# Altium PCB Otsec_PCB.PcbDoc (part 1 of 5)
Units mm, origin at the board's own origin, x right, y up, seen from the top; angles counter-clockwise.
Board outline 170 x 120 mm, 3 copper layers (Top Layer, Internal Plane 1, Bottom Layer), stack 1.608 mm thick; 1624 components, 0 nets, 5478 pads, 0 vias.
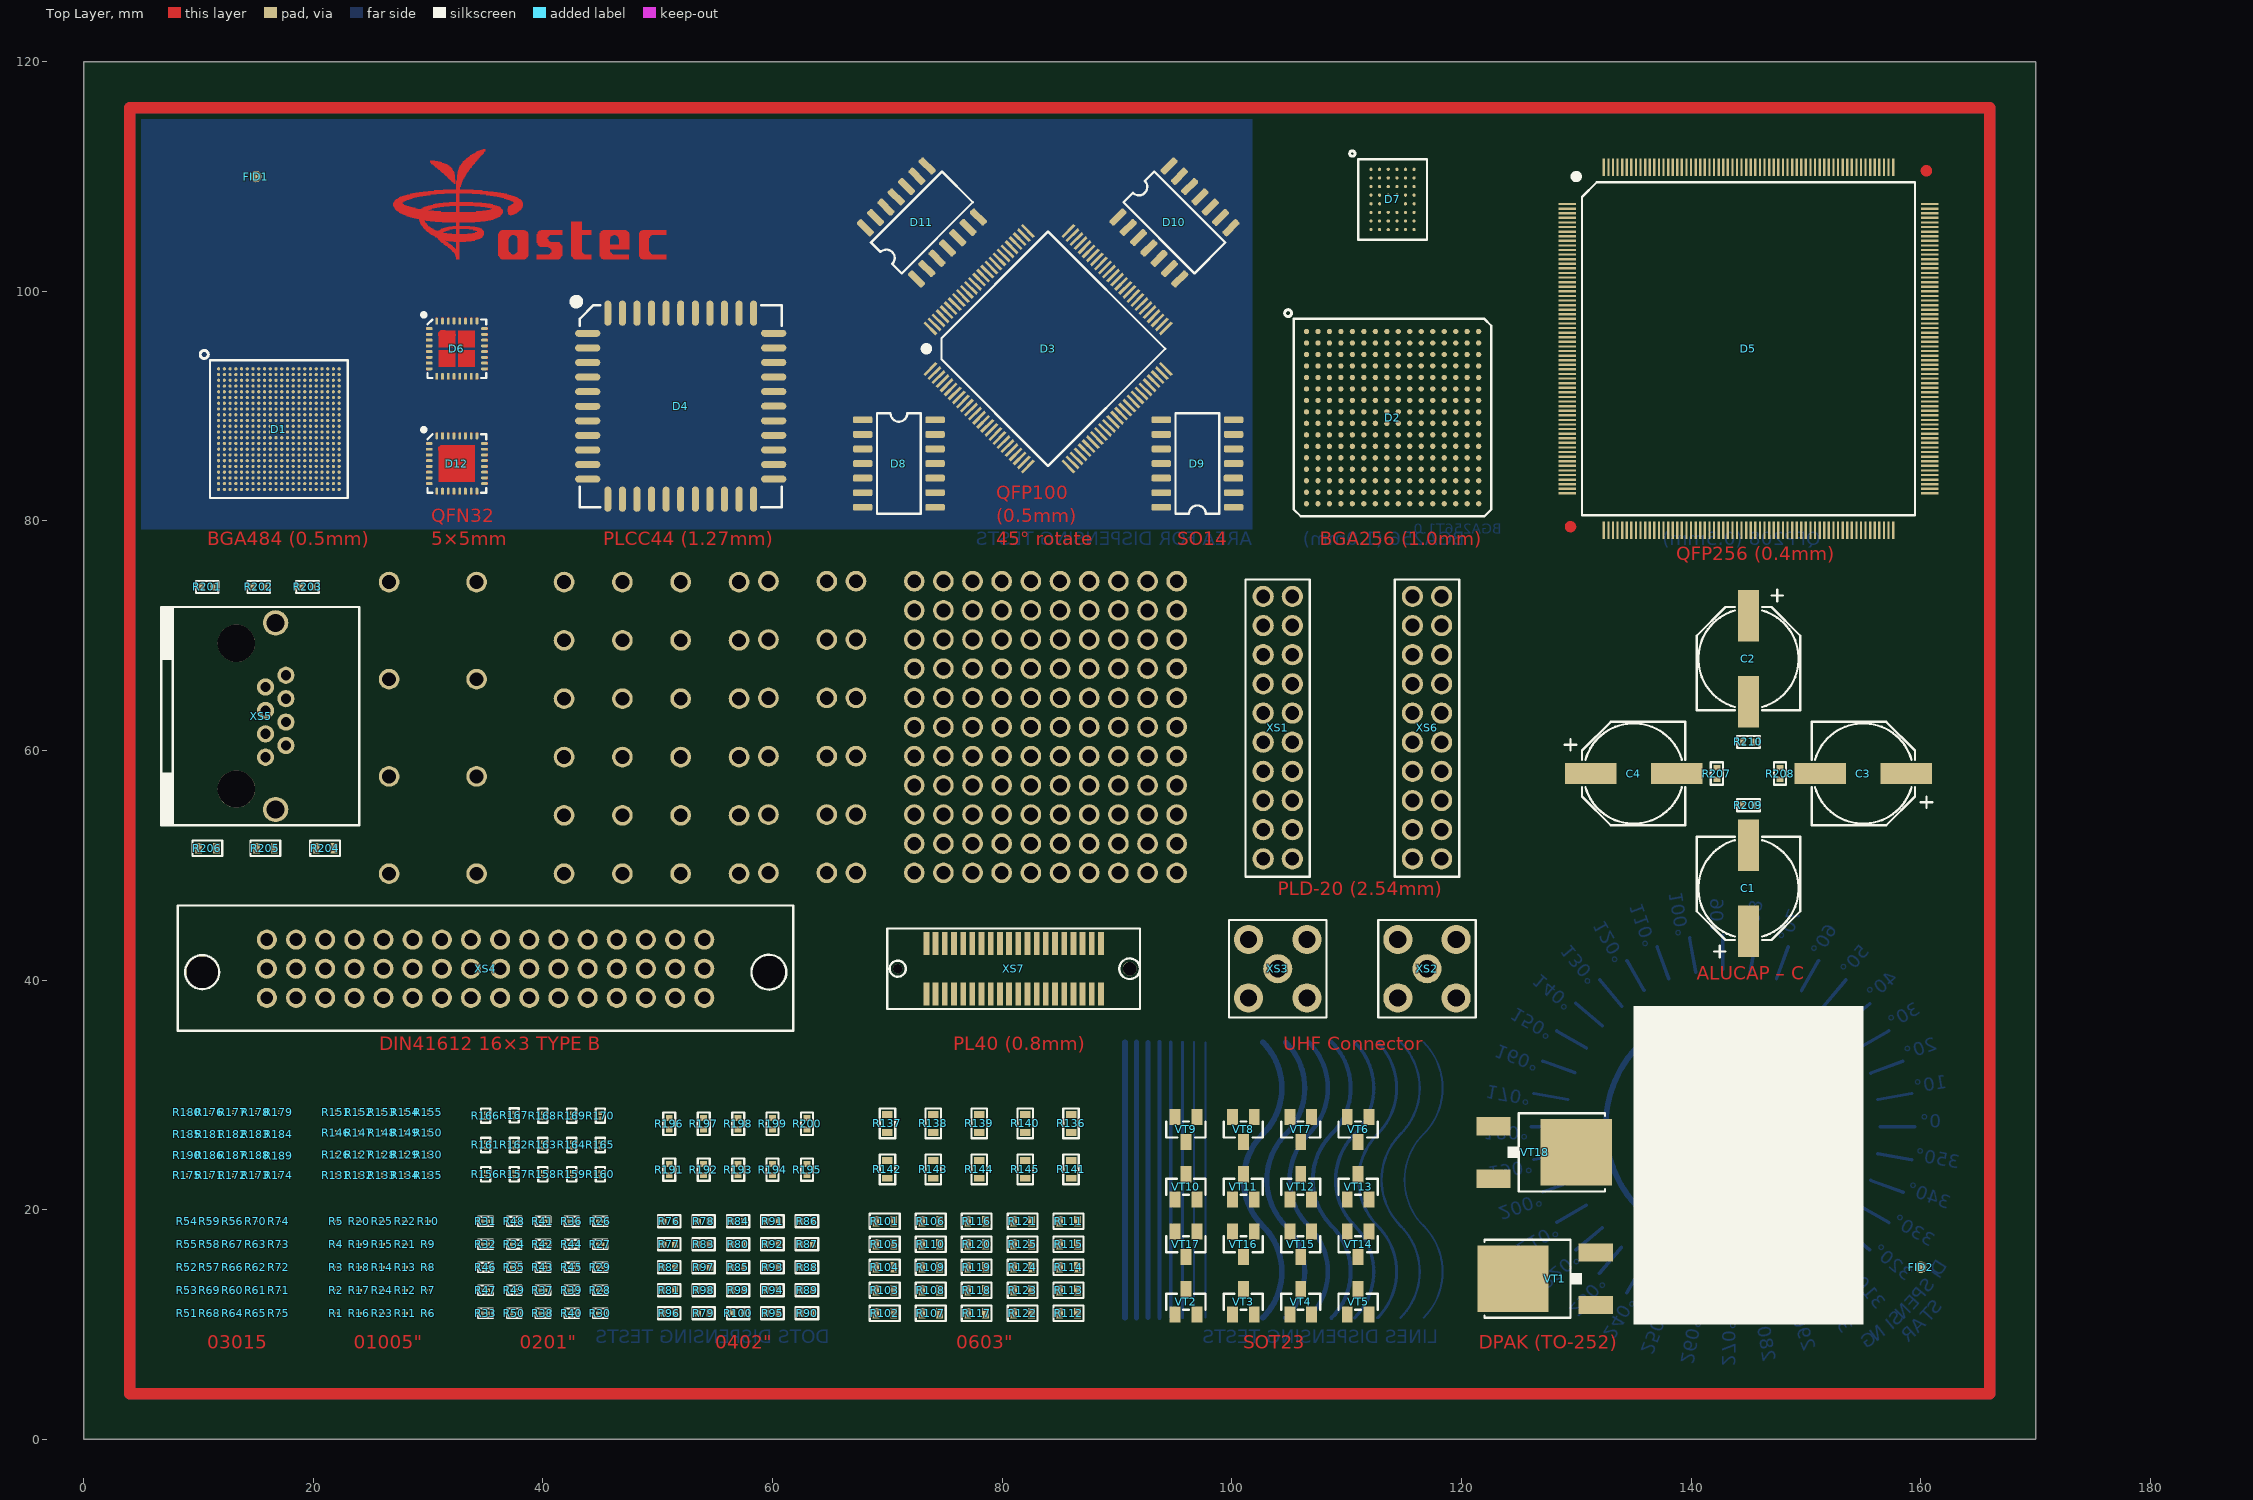
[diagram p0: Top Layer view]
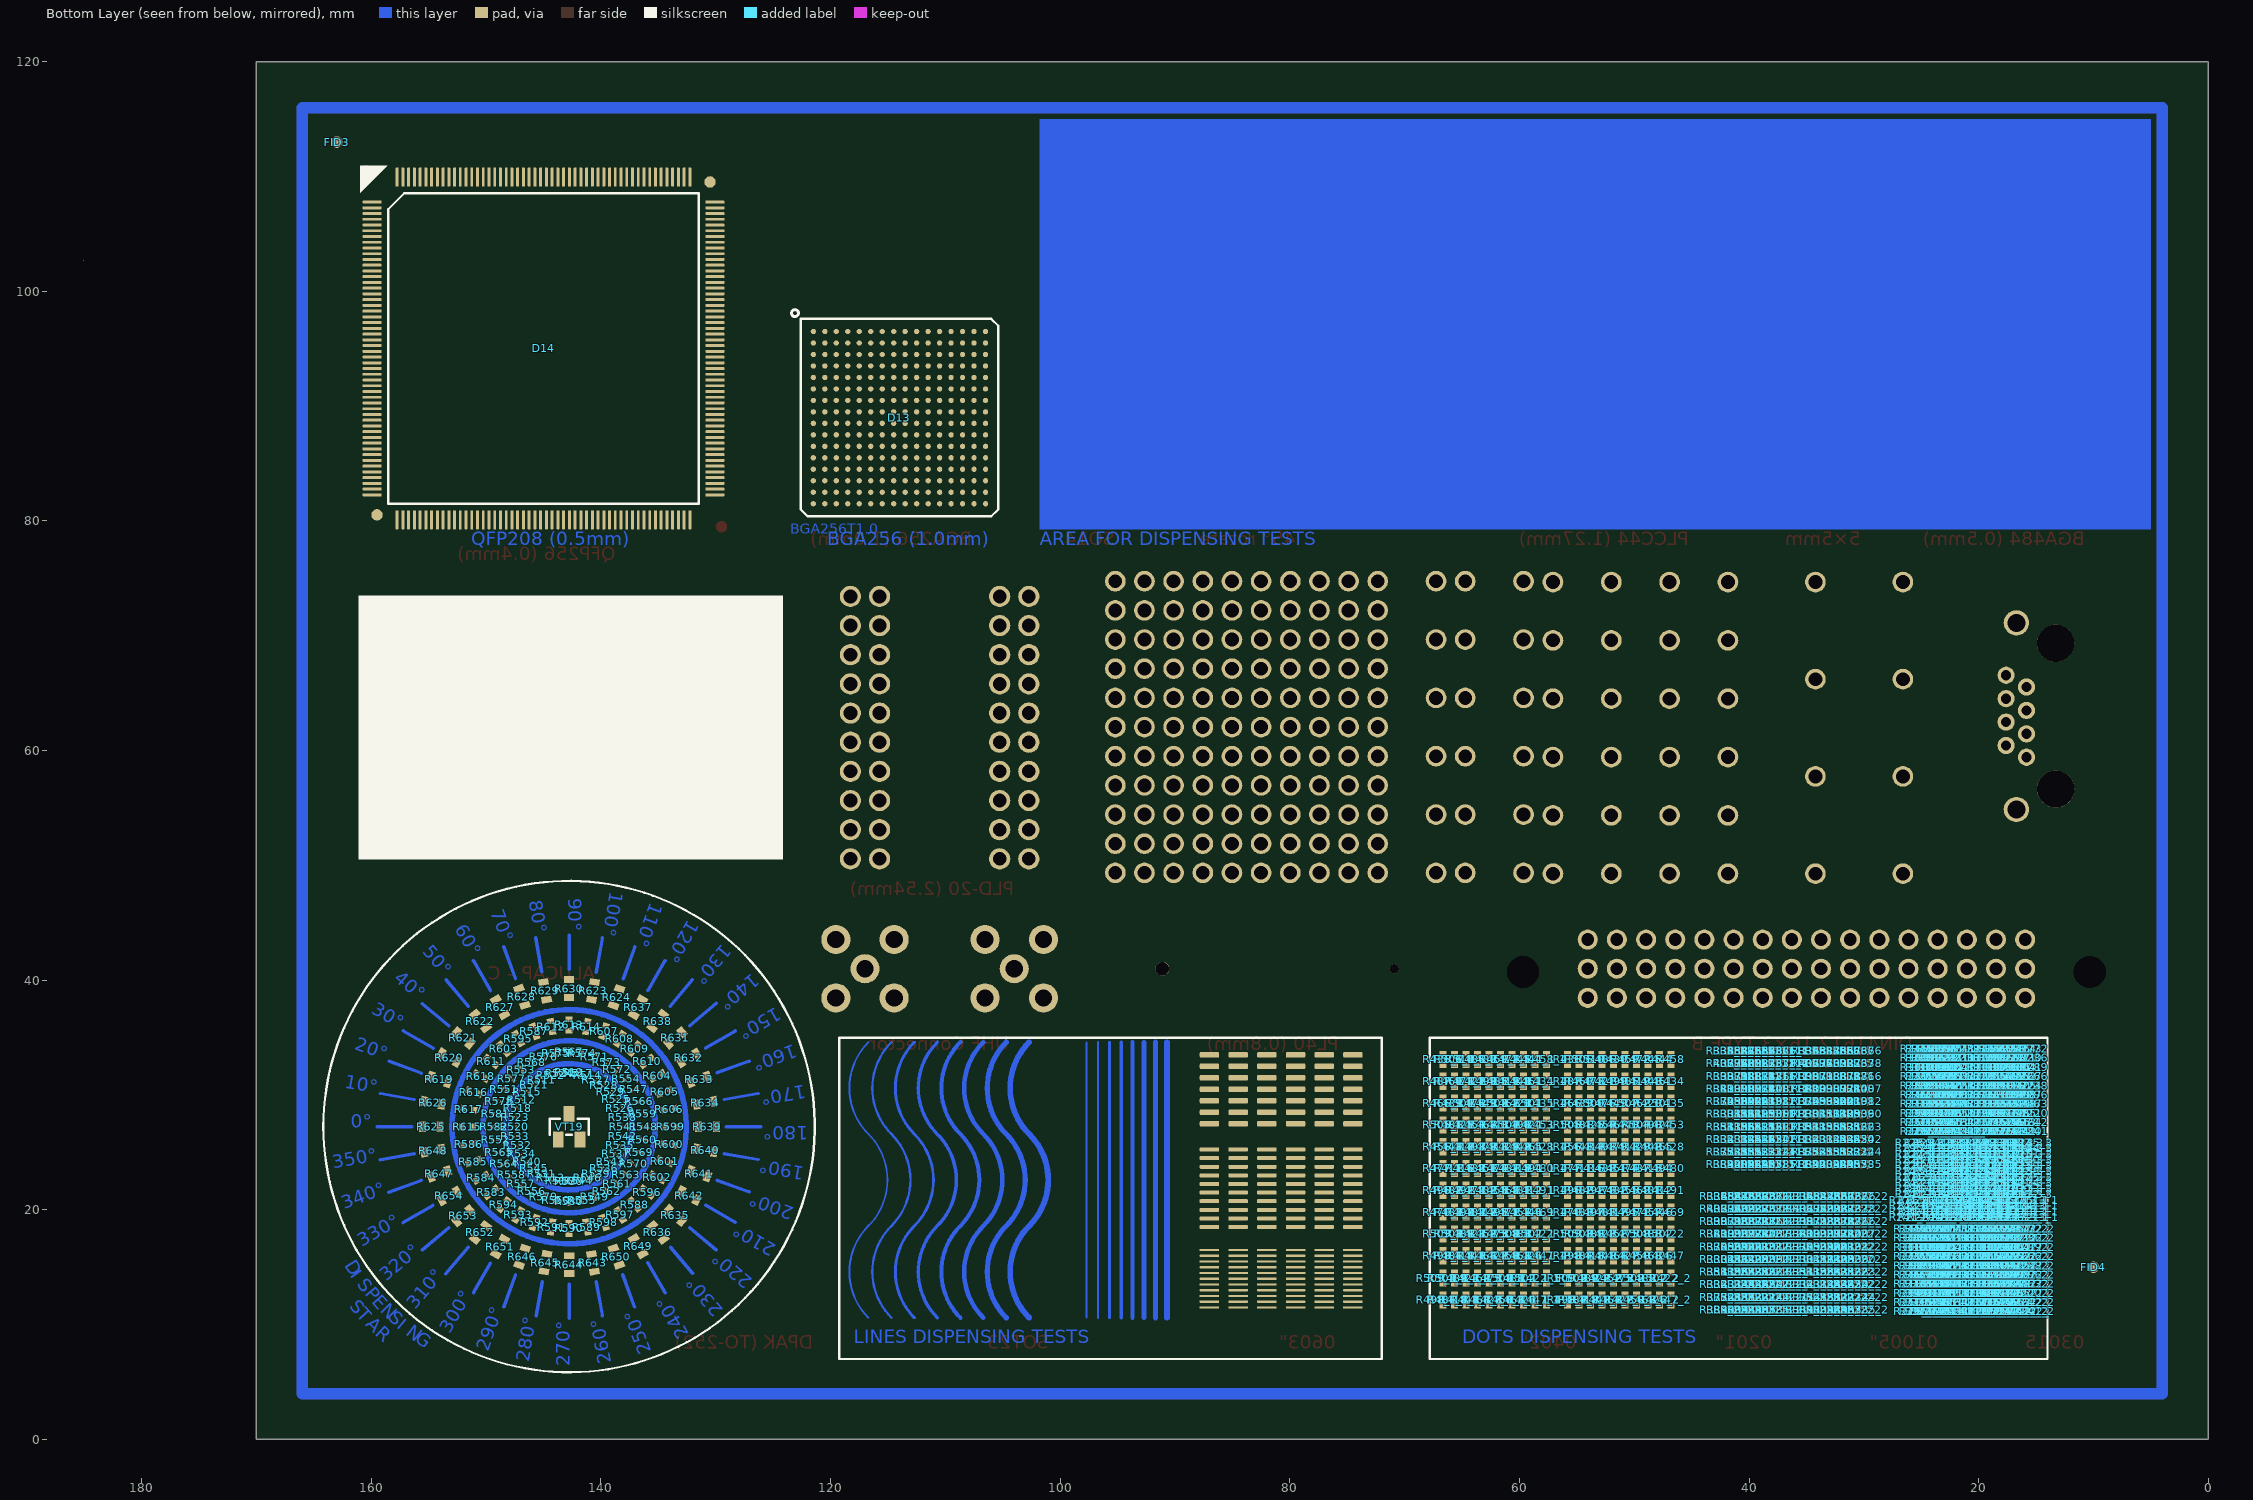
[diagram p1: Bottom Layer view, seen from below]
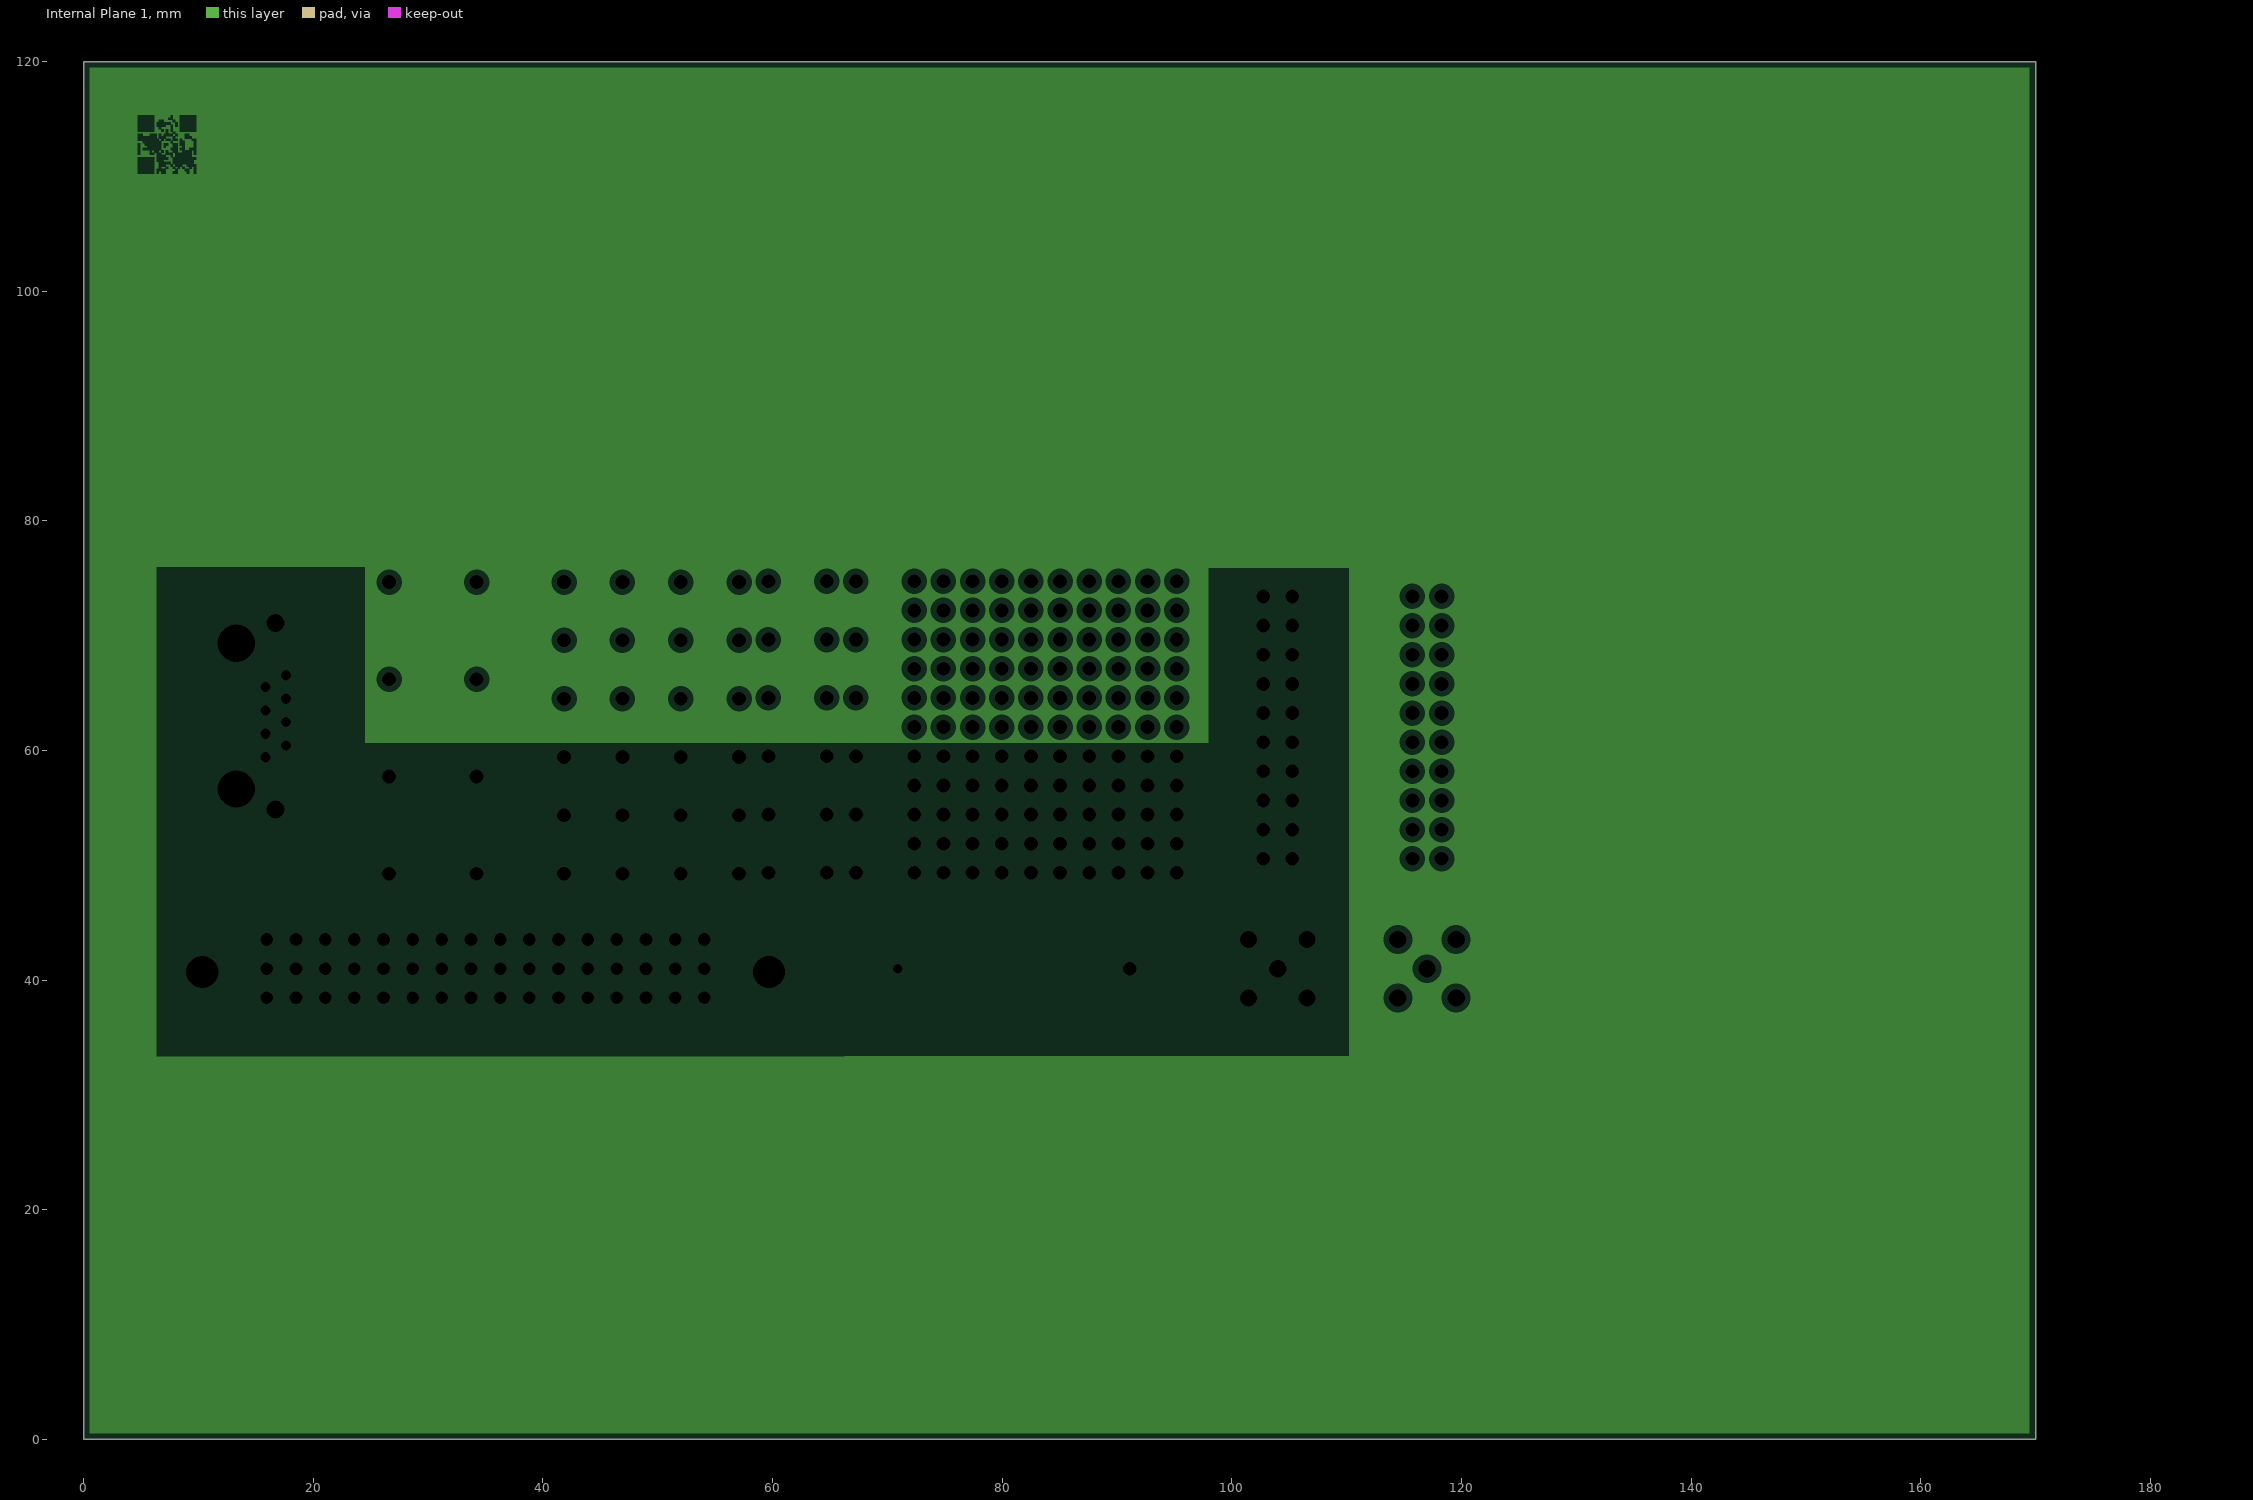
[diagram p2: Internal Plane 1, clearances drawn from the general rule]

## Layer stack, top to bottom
Top Solder: solder mask 0.0102, Solder Resist, Dk 3.5
Top Layer: signal copper 0.036
Dielectric 1: core 0.75, FR-4, Dk 4.2
Internal Plane 1: plane copper 0.036
Dielectric 2: prepreg 0.75, Dk 4.2
Bottom Layer: signal copper 0.0356
Bottom Solder: solder mask 0.0102, Solder Resist, Dk 3.5

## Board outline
0,0 170,0 170,120 0,120

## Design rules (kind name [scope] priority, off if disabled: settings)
Clearance [All] p1: gap=0.254 ignorepadtopadclearanceinfootprint=FALSE except(0: Arc-Hole Track-Hole SMDPad-Hole THPad-Hole Via-Hole Fill-Hole Poly-Hole Region-Hole Text-Hole)
PlaneClearance [All] p1: clearance=0.508
PlaneConnect [All] p1: planeconnectstyle=Relief reliefexpansion=0.508 reliefentries=4 reliefconductorwidth=0.254 reliefairgap=0.254
PolygonConnect [All] p1: connectstyle=Relief reliefconductorwidth=0.254 reliefentries=4 polygonreliefangle="90 Angle" airgapwidth=0.254
RoomDefinition Sheet1 [InComponentClass('Sheet1')] p1: confinementstyle=ConfineIn formatcopy=TRUE lockcomponents=FALSE outline -170,-130 -119.2,-130 -119.2,-104.6 -170,-104.6
RoutingVias [All] p1: holewidth=0.711 width=1.27 viastyle="Through Hole" minholewidth=0.711 minwidth=1.27 maxholewidth=0.711 maxwidth=1.27
SolderMaskExpansion [All] p1: expansion=0.102
Width [All] p1: maxlimit=0.254 minlimit=0.254 preferedwidth=0.254
28 further rules are at their usual default settings.

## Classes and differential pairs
component class Sheet1: C1 C2 C3 C4 D1 D2 D3 D4 D5 D6 D7 D8 D9 D10 D11 D12 D13 D14 FID1 FID2 FID3 FID4 R1 R2 R3 R4 R5 R6 R7 R8 R9 R10 R11 R12 R13 R14 R15 R16 R17 R18 R19 R20 R21 R22 R23 R24 R25 R26 R27 R28 R29 R30 R31 R32 R33 R34 R35 R36 R37 R38 R39 R40 R41 R42 R43 R44 R45 R46 R47 R48 R49 R50 R51 R52 R53 R54 R55 R56 R57 R58 R59 R60 R61 R62 R63 R64 R65 R66 R67 R68 R69 R70 R71 R72 R73 R74 R75 R76 R77 R78 R79 R80 R81 R82 R83 R84 R85 R86 R87 R88 R89 R90 R91 R92 R93 R94 R95 R96 R97 R98 R99 R100 R101 R102 R103 R104 R105 R106 R107 R108 R109 R110 R111 R112 R113 R114 R115 R116 R117 R118 R119 R120 R121 R122 R123 R124 R125 R126 R127 R128 R129 R130 R131 R132 R133 R134 R135 R136 R137 R138 R139 R140 R141 R142 R143 R144 R145 R146 R147 R148 R149 R150 R151 R152 R153 R154 R155 R156 R157 R158 R159 R160 R161 R162 R163 R164 R165 R166 R167 R168 R169 R170 R171 R172 R173 R174 R175 R176 R177 R178 R179 R180 R181 R182 R183 R184 R185 R186 R187 R188 R189 R190 R191 R192 R193 R194 R195 R196 R197 R198 R199 R200 R201 R202 R203 R204 R205 R206 R207 R208 R209 R210 R211 R212 R213 R214 R215 R216 R217 R218 R219 R220 R221 R222 R223 R224 R225 R226 R227 R228 R229 R230 R231 R232 R233 R234 R235 R236 R237 R238 R239 R240 R241 R242 R243 R244 R245 R246 R247 R248 R249 R250 R251 R252 R253 R254 R255 R256 R257 R258 R259 R260 R261 R262 R263 R264 R265 R266 R267 R268 R269 R270 R271 R272 R273 R274 R275 R276 R277 R278 R279 R280 R281 R282 R283 R284 R285 R286 R287 R288 R289 R290 R291 R292 R293 R294 R295 R296 R297 R298 R299 R300 R301 R302 R303 R304 R305 R306 R307 R308 R309 R310 R311 R312 R313 R314 R315 R316 R317 R318 R319 R320 R321 R322 R323 R324 R325 R326 R327 R328 R329 R330 R331 R332 R333 R334 R335 R336 R337 R338 R339 R340 R341 R342 R343 R344 R345 R346 R347 R348 R349 R350 R351 R352 R353 R354 R355 R356 R357 R358 R359 R360 R361 R362 R363 R364 R365 R366 R367 R368 R369 R370 R371 R372 R373 R374 R375 R376 R377 R378 R379 R380 R381 R382 R383 R384 R385 R386 R387 R388 R389 R390 R391 R392 R393 R394 R395 R396 R397 R398 R399 R400 R401 R402 R403 R404 R405 R406 R407 R408 R409 R410 R411 R412 R413 R414 R415 R416 R417 R418 R419 R420 R421 R422 R423 R424 R425 R426 R427 R428 R429 R430 R431 R432 R433 R434 R435 R436 R437 R438 R439 R440 R441 R442 R443 R444 R445 R446 R447 R448 R449 R450 R451 R452 R453 R454 R455 R456 R457 R458 R459 R460 R461 R462 R463 R464 R465 R466 R467 R468 R469 R470 R471 R472 R473 R474 R475 R476 R477 R478 R479 R480 R481 R482 R483 R484 R485 R486 R487 R488 R489 R490 R491 R492 R493 R494 R495 R496 R497 R498 R499 R500 R501 R502 R503 R504 R505 R506 R507 R508 R509 R510 R511 R512 R513 R514 R515 R516 R517 R518 R519 R520 R521 R522 R523 R524 R525 R526 R527 R528 R529 R530 R531 R532 R533 R534 R535 R536 R537 R538 R539 R540 R541 R542 R543 R544 R545 R546 R547 R548 R549 R550 R551 R552 R553 R554 R555 R556 R557 R558 R559 R560 R561 R562 R563 R564 R565 R566 R567 R568 R569 R570 R571 R572 R573 R574 R575 R576 R577 R578 R579 R580 R581 R582 R583 R584 R585 R586 R587 R588 R589 R590 R591 R592 R593 R594 R595 R596 R597 R598 R599 R600 R601 R602 R603 R604 R605 R606 R607 R608 R609 R610 R611 R612 R613 R614 R615 R616 R617 R618 R619 R620 R621 R622 R623 R624 R625 R626 R627 R628 R629 R630 R631 R632 R633 R634 R635 R636 R637 R638 R639 R640 R641 R642 R643 R644 R645 R646 R647 R648 R649 R650 R651 R652 R653 R654 VT1 VT2 VT3 VT4 VT5 VT6 VT7 VT8 VT9 VT10 VT11 VT12 VT13 VT14 VT15 VT16 VT17 VT18 VT19 XS1 XS2 XS3 XS4 XS5 XS6 XS7

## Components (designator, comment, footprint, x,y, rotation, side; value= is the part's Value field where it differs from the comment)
C1 "*" "AluCAP 8x10" 145,48 r90 top
C2 "*" "AluCAP 8x10" 145,68 r270 top
C3 "*" "AluCAP 8x10" 155,58 r180 top
C4 "*" "AluCAP 8x10" 135,58 r0 top
D1 "LBGA484T.5-DC229B" BGA484-0.5 17,88 r0 top
D2 "BGA256T1.0" BGA256 114,89 r0 top
D3 "LQFP100T19.7" QFP100_0.5 84,95 r45 top
D4 "PLCC44" PLCC44 52,90 r0 top
D5 "QFP256T15.7-2.6" QFP256 145,95 r0 top
D6 "QFN32T.5F" QFN32 32.5,95 r0 top
D7 "BGA46T.75-DC24" uBGA46 114,108 r0 top
D8 "SO14" SO14 71,85 r0 top
D9 "SO14" SO14 97,85 r180 top
D10 "SO14" SO14 95,106 r45 top
D11 "SO14" SO14 73,106 r135 top
D12 "QFN32T.5F" QFN32_2 32.5,85 r0 top
D13 "BGA256T1.0" BGA256 114,89 r180 bottom
D14 "QFP208T19.7-2.6" QFP208 145,95.025 r180 bottom
FID1 "FID" FID#1 15,110 r90 top
FID2 "FID" FID#2 162.325,8.825 r90 top
FID3 "FID" FID#3 163.825,108.425 r90 bottom
FID4 "FID" FID#1 10,15 r90 bottom
R1 "*" R01005 22,11 r0 top
R2 "*" R01005 22,13 r180 top
R3 "*" R01005 22,15 r180 top
R4 "*" R01005 22,17 r180 top
R5 "*" R01005 22,19 r180 top
R6 "*" R01005 30,11 r180 top
R7 "*" R01005 30,13 r180 top
R8 "*" R01005 30,15 r180 top
R9 "*" R01005 30,17 r180 top
R10 "*" R01005 30,19 r180 top
R11 "*" R01005 28,11 r180 top
R12 "*" R01005 28,13 r180 top
R13 "*" R01005 28,15 r180 top
R14 "*" R01005 26,15 r180 top
R15 "*" R01005 26,17 r180 top
R16 "*" R01005 24,11 r180 top
R17 "*" R01005 24,13 r180 top
R18 "*" R01005 24,15 r180 top
R19 "*" R01005 24,17 r180 top
R20 "*" R01005 24,19 r180 top
R21 "*" R01005 28,17 r180 top
R22 "*" R01005 28,19 r180 top
R23 "*" R01005 26,11 r180 top
R24 "*" R01005 26,13 r180 top
R25 "*" R01005 26,19 r180 top
R26 "*" R0201 45,19 r0 top
R27 "*" R0201 45,17 r0 top
R28 "*" R0201 45,13 r0 top
R29 "*" R0201 45,15 r0 top
R30 "*" R0201 45,11 r0 top
R31 "*" R0201 35,19 r0 top
R32 "*" R0201 35,17 r0 top
R33 "*" R0201 35,11 r0 top
R34 "*" R0201 37.5,17 r0 top
R35 "*" R0201 37.5,15 r0 top
R36 "*" R0201 42.5,19 r0 top
R37 "*" R0201 40,13 r0 top
R38 "*" R0201 40,11 r0 top
R39 "*" R0201 42.5,13 r0 top
R40 "*" R0201 42.5,11 r0 top
R41 "*" R0201 40,19 r0 top
R42 "*" R0201 40,17 r0 top
R43 "*" R0201 40,15 r0 top
R44 "*" R0201 42.5,17 r0 top
R45 "*" R0201 42.5,15 r0 top
R46 "*" R0201 35,15 r0 top
R47 "*" R0201 35,13 r0 top
R48 "*" R0201 37.5,19 r0 top
R49 "*" R0201 37.5,13 r0 top
R50 "*" R0201 37.5,11 r0 top
R51 "*" R03015 9,11 r180 top
R52 "*" R03015 9,15 r180 top
R53 "*" R03015 9,13 r180 top
R54 "*" R03015 9,19 r180 top
R55 "*" R03015 9,17 r180 top
R56 "*" R03015 13,19 r180 top
R57 "*" R03015 11,15 r180 top
R58 "*" R03015 11,17 r180 top
R59 "*" R03015 11,19 r180 top
R60 "*" R03015 13,13 r180 top
R61 "*" R03015 15,13 r180 top
R62 "*" R03015 15,15 r180 top
R63 "*" R03015 15,17 r180 top
R64 "*" R03015 13,11 r180 top
R65 "*" R03015 15,11 r180 top
R66 "*" R03015 13,15 r180 top
R67 "*" R03015 13,17 r180 top
R68 "*" R03015 11,11 r180 top
R69 "*" R03015 11,13 r180 top
R70 "*" R03015 15,19 r180 top
R71 "*" R03015 17,13 r180 top
R72 "*" R03015 17,15 r180 top
R73 "*" R03015 17,17 r180 top
R74 "*" R03015 17,19 r180 top
R75 "*" R03015 17,11 r180 top
R76 "*" R0402 51,19 r0 top
R77 "*" R0402 51,17 r0 top
R78 "*" R0402 54,19 r0 top
R79 "*" R0402 54,11 r0 top
R80 "*" R0402 57,17 r0 top
R81 "*" R0402 51,13 r0 top
R82 "*" R0402 51,15 r0 top
R83 "*" R0402 54,17 r0 top
R84 "*" R0402 57,19 r0 top
R85 "*" R0402 57,15 r0 top
R86 "*" R0402 63,19 r0 top
R87 "*" R0402 63,17 r0 top
R88 "*" R0402 63,15 r0 top
R89 "*" R0402 63,13 r0 top
R90 "*" R0402 63,11 r0 top
R91 "*" R0402 60,19 r0 top
R92 "*" R0402 60,17 r0 top
R93 "*" R0402 60,15 r0 top
R94 "*" R0402 60,13 r0 top
R95 "*" R0402 60,11 r0 top
R96 "*" R0402 51,11 r0 top
R97 "*" R0402 54,15 r0 top
R98 "*" R0402 54,13 r0 top
R99 "*" R0402 57,13 r0 top
R100 "*" R0402 57,11 r0 top
R101 "*" R0603 69.8,19 r180 top
R102 "*" R0603 69.8,11 r180 top
R103 "*" R0603 69.8,13 r180 top
R104 "*" R0603 69.8,15 r180 top
R105 "*" R0603 69.8,17 r180 top
R106 "*" R0603 73.8,19 r180 top
R107 "*" R0603 73.8,11 r180 top
R108 "*" R0603 73.8,13 r180 top
R109 "*" R0603 73.8,15 r180 top
R110 "*" R0603 73.8,17 r180 top
R111 "*" R0603 85.8,19 r180 top
R112 "*" R0603 85.8,11 r180 top
R113 "*" R0603 85.8,13 r180 top
R114 "*" R0603 85.8,15 r180 top
R115 "*" R0603 85.8,17 r180 top
R116 "*" R0603 77.8,19 r180 top
R117 "*" R0603 77.8,11 r180 top
R118 "*" R0603 77.8,13 r180 top
R119 "*" R0603 77.8,15 r180 top
R120 "*" R0603 77.8,17 r180 top
R121 "*" R0603 81.8,19 r180 top
R122 "*" R0603 81.8,11 r180 top
R123 "*" R0603 81.8,13 r180 top
R124 "*" R0603 81.8,15 r180 top
R125 "*" R0603 81.8,17 r180 top
R126 "*" R01005 22,24.8 r90 top
R127 "*" R01005 24,24.8 r90 top
R128 "*" R01005 26,24.8 r90 top
R129 "*" R01005 28,24.8 r90 top
R130 "*" R01005 30,24.8 r90 top
R131 "*" R01005 22,23 r90 top
R132 "*" R01005 24,23 r90 top
R133 "*" R01005 26,23 r90 top
R134 "*" R01005 28,23 r90 top
R135 "*" R01005 30,23 r90 top
R136 "*" R0603 86,27.5 r90 top
R137 "*" R0603 70,27.5 r90 top
R138 "*" R0603 74,27.5 r90 top
R139 "*" R0603 78,27.5 r90 top
R140 "*" R0603 82,27.5 r90 top
R141 "*" R0603 86,23.5 r90 top
R142 "*" R0603 70,23.5 r90 top
R143 "*" R0603 74,23.5 r90 top
R144 "*" R0603 78,23.5 r90 top
R145 "*" R0603 82,23.5 r90 top
R146 "*" R01005 22,26.7 r90 top
R147 "*" R01005 24,26.7 r90 top
R148 "*" R01005 26,26.7 r90 top
R149 "*" R01005 28,26.7 r90 top
R150 "*" R01005 30,26.7 r90 top
R151 "*" R01005 22,28.5 r90 top
R152 "*" R01005 24,28.5 r90 top
R153 "*" R01005 26,28.5 r90 top
R154 "*" R01005 28,28.5 r90 top
R155 "*" R01005 30,28.5 r90 top
R156 "*" R0201 35,23.1 r90 top
R157 "*" R0201 37.5,23.1 r90 top
R158 "*" R0201 40,23.1 r90 top
R159 "*" R0201 42.5,23.1 r90 top
R160 "*" R0201 45,23.1 r90 top
R161 "*" R0201 35,25.65 r90 top
R162 "*" R0201 37.5,25.65 r90 top
R163 "*" R0201 40,25.65 r90 top
R164 "*" R0201 42.5,25.65 r90 top
R165 "*" R0201 45,25.65 r90 top
R166 "*" R0201 35,28.2 r90 top
R167 "*" R0201 37.5,28.225 r90 top
R168 "*" R0201 40,28.2 r90 top
R169 "*" R0201 42.5,28.2 r90 top
R170 "*" R0201 45,28.2 r90 top
R171 "*" R03015 11,23 r90 top
R172 "*" R03015 13,23 r90 top
R173 "*" R03015 15,23 r90 top
R174 "*" R03015 17,23 r90 top
R175 "*" R03015 9,23 r90 top
R176 "*" R03015 11,28.5 r90 top
R177 "*" R03015 13,28.5 r90 top
R178 "*" R03015 15,28.5 r90 top
R179 "*" R03015 17,28.5 r90 top
R180 "*" R03015 9,28.5 r90 top
R181 "*" R03015 11,26.6 r90 top
R182 "*" R03015 13,26.6 r90 top
R183 "*" R03015 15,26.6 r90 top
R184 "*" R03015 17,26.6 r90 top
R185 "*" R03015 9,26.6 r90 top
R186 "*" R03015 11,24.75 r90 top
R187 "*" R03015 13,24.75 r90 top
R188 "*" R03015 15,24.75 r90 top
R189 "*" R03015 17,24.72 r90 top
R190 "*" R03015 9,24.75 r90 top
R191 "*" R0402 51,23.5 r90 top
R192 "*" R0402 54,23.5 r90 top
R193 "*" R0402 57,23.5 r90 top
R194 "*" R0402 60,23.5 r90 top
R195 "*" R0402 63,23.5 r90 top
R196 "*" R0402 51,27.5 r90 top
R197 "*" R0402 54,27.5 r90 top
R198 "*" R0402 57,27.5 r90 top
R199 "*" R0402 60,27.5 r90 top
R200 "*" R0402 63,27.5 r90 top
R201 "*" R0402 10.75,74.25 r180 top
R202 "*" R0402 15.25,74.25 r180 top
R203 "*" R0402 19.5,74.25 r180 top
R204 "*" R0603 21,51.5 r0 top
R205 "*" R0603 15.8,51.5 r0 top
R206 "*" R0603 10.75,51.5 r0 top
R207 "*" R0402 142.25,58 r90 top
R208 "*" R0402 147.75,58 r90 top
R209 "*" R0402 145,55.25 r180 top
R210 "*" R0402 145,60.75 r0 top
R211 "*" R01005 15.675,28.425 r90 bottom
R211_1 "*" R01005 21.05,28.425 r90 bottom
R211_1_1 "*" R01005 21.05,12.75 r90 bottom
R211_2 "*" R01005 15.675,12.75 r90 bottom
R211_3 "*" R01005 20.925,21.85 r180 bottom
R211_3_1 "*" R01005 23.325,21.85 r180 bottom
R211_3_1_1 "*" R01005 23.325,19.85 r180 bottom
R211_3_2 "*" R01005 20.925,19.85 r180 bottom
R212 "*" R01005 15.175,27.625 r90 bottom
R212_1 "*" R01005 20.55,27.625 r90 bottom
R212_1_1 "*" R01005 20.55,11.95 r90 bottom
R212_2 "*" R01005 15.175,11.95 r90 bottom
R212_3 "*" R01005 21.725,21.35 r180 bottom
R212_3_1 "*" R01005 24.125,21.35 r180 bottom
R212_3_1_1 "*" R01005 24.125,19.35 r180 bottom
R212_3_2 "*" R01005 21.725,19.35 r180 bottom
R213 "*" R01005 16.175,27.625 r90 bottom
R213_1 "*" R01005 21.55,27.625 r90 bottom
R213_1_1 "*" R01005 21.55,11.95 r90 bottom
R213_2 "*" R01005 16.175,11.95 r90 bottom
R213_3 "*" R01005 21.725,22.35 r180 bottom
R213_3_1 "*" R01005 24.125,22.35 r180 bottom
R213_3_1_1 "*" R01005 24.125,20.35 r180 bottom
R213_3_2 "*" R01005 21.725,20.35 r180 bottom
R214 "*" R01005 17.675,27.625 r90 bottom
R214_1 "*" R01005 23.05,27.625 r90 bottom
R214_1_1 "*" R01005 23.05,11.95 r90 bottom
R214_2 "*" R01005 17.675,11.95 r90 bottom
R214_3 "*" R01005 21.725,23.85 r180 bottom
R214_3_1 "*" R01005 24.125,23.85 r180 bottom
R215 "*" R01005 18.675,27.625 r90 bottom
R215_1 "*" R01005 24.05,27.625 r90 bottom
R215_1_1 "*" R01005 24.05,11.95 r90 bottom
R215_2 "*" R01005 18.675,11.95 r90 bottom
R215_3 "*" R01005 21.725,24.85 r180 bottom
R215_3_1 "*" R01005 24.125,24.85 r180 bottom
R216 "*" R01005 17.175,30.825 r90 bottom
R216_1 "*" R01005 22.55,30.825 r90 bottom
R216_1_1 "*" R01005 22.55,15.15 r90 bottom
R216_2 "*" R01005 17.175,15.15 r90 bottom
R216_3 "*" R01005 18.525,23.35 r180 bottom
R217 "*" R01005 17.675,30.825 r90 bottom
R217_1 "*" R01005 23.05,30.825 r90 bottom
R217_1_1 "*" R01005 23.05,15.15 r90 bottom
R217_2 "*" R01005 17.675,15.15 r90 bottom
R217_3 "*" R01005 18.525,23.85 r180 bottom
R218 "*" R01005 19.175,29.225 r90 bottom
R218_1 "*" R01005 24.55,29.225 r90 bottom
R218_1_1 "*" R01005 24.55,13.55 r90 bottom
R218_2 "*" R01005 19.175,13.55 r90 bottom
R218_3 "*" R01005 20.125,25.35 r180 bottom
R219 "*" R01005 19.675,29.225 r90 bottom
R219_1 "*" R01005 25.05,29.225 r90 bottom
R219_1_1 "*" R01005 25.05,13.55 r90 bottom
R219_2 "*" R01005 19.675,13.55 r90 bottom
R219_3 "*" R01005 20.125,25.85 r180 bottom
R220 "*" R01005 15.175,28.425 r90 bottom
R220_1 "*" R01005 20.55,28.425 r90 bottom
R220_1_1 "*" R01005 20.55,12.75 r90 bottom
R220_2 "*" R01005 15.175,12.75 r90 bottom
R220_3 "*" R01005 20.925,21.35 r180 bottom
R220_3_1 "*" R01005 23.325,21.35 r180 bottom
R220_3_1_1 "*" R01005 23.325,19.35 r180 bottom
R220_3_2 "*" R01005 20.925,19.35 r180 bottom
R221 "*" R01005 16.175,33.225 r90 bottom
R221_1 "*" R01005 21.55,33.225 r90 bottom
R221_1_1 "*" R01005 21.55,17.55 r90 bottom
R221_2 "*" R01005 16.175,17.55 r90 bottom
R221_3 "*" R01005 16.125,22.35 r180 bottom
R221_3_1 "*" R01005 16.125,20.35 r180 bottom
R222 "*" R01005 17.175,33.225 r90 bottom
R222_1 "*" R01005 22.55,33.225 r90 bottom
R222_1_1 "*" R01005 22.55,17.55 r90 bottom
R222_2 "*" R01005 17.175,17.55 r90 bottom
R222_3 "*" R01005 16.125,23.35 r180 bottom
R223 "*" R01005 17.675,33.225 r90 bottom
R223_1 "*" R01005 23.05,33.225 r90 bottom
R223_1_1 "*" R01005 23.05,17.55 r90 bottom
R223_2 "*" R01005 17.675,17.55 r90 bottom
R223_3 "*" R01005 16.125,23.85 r180 bottom
R224 "*" R01005 15.675,30.825 r90 bottom
R224_1 "*" R01005 21.05,30.825 r90 bottom
R224_1_1 "*" R01005 21.05,15.15 r90 bottom
R224_2 "*" R01005 15.675,15.15 r90 bottom
R224_3 "*" R01005 18.525,21.85 r180 bottom
R224_3_1 "*" R01005 18.525,19.85 r180 bottom
R225 "*" R01005 16.175,30.825 r90 bottom
R225_1 "*" R01005 21.55,30.825 r90 bottom
R225_1_1 "*" R01005 21.55,15.15 r90 bottom
R225_2 "*" R01005 16.175,15.15 r90 bottom
R225_3 "*" R01005 18.525,22.35 r180 bottom
R225_3_1 "*" R01005 18.525,20.35 r180 bottom
R226 "*" R01005 18.175,26.825 r90 bottom
R226_1 "*" R01005 23.55,26.825 r90 bottom
R226_1_1 "*" R01005 23.55,11.15 r90 bottom
R226_2 "*" R01005 18.175,11.15 r90 bottom
R226_3 "*" R01005 22.525,24.35 r180 bottom
R226_3_1 "*" R01005 24.925,24.35 r180 bottom
R227 "*" R01005 18.675,26.825 r90 bottom
R227_1 "*" R01005 24.05,26.825 r90 bottom
R227_1_1 "*" R01005 24.05,11.15 r90 bottom
R227_2 "*" R01005 18.675,11.15 r90 bottom
R227_3 "*" R01005 22.525,24.85 r180 bottom
R227_3_1 "*" R01005 24.925,24.85 r180 bottom
R228 "*" R01005 19.675,26.825 r90 bottom
R228_1 "*" R01005 25.05,26.825 r90 bottom
R228_1_1 "*" R01005 25.05,11.15 r90 bottom
R228_2 "*" R01005 19.675,11.15 r90 bottom
R228_3 "*" R01005 22.525,25.85 r180 bottom
R228_3_1 "*" R01005 24.925,25.85 r180 bottom
R229 "*" R01005 17.675,26.825 r90 bottom
R229_1 "*" R01005 23.05,26.825 r90 bottom
R229_1_1 "*" R01005 23.05,11.15 r90 bottom
R229_2 "*" R01005 17.675,11.15 r90 bottom
R229_3 "*" R01005 22.525,23.85 r180 bottom
R229_3_1 "*" R01005 24.925,23.85 r180 bottom
R230 "*" R01005 15.675,33.225 r90 bottom
R230_1 "*" R01005 21.05,33.225 r90 bottom
R230_1_1 "*" R01005 21.05,17.55 r90 bottom
R230_2 "*" R01005 15.675,17.55 r90 bottom
R230_3 "*" R01005 16.125,21.85 r180 bottom
R230_3_1 "*" R01005 16.125,19.85 r180 bottom
R231 "*" R01005 19.175,31.625 r90 bottom
R231_1 "*" R01005 24.55,31.625 r90 bottom
R231_1_1 "*" R01005 24.55,15.95 r90 bottom
R231_2 "*" R01005 19.175,15.95 r90 bottom
R231_3 "*" R01005 17.725,25.35 r180 bottom
R232 "*" R01005 17.175,29.225 r90 bottom
R232_1 "*" R01005 22.55,29.225 r90 bottom
R232_1_1 "*" R01005 22.55,13.55 r90 bottom
R232_2 "*" R01005 17.175,13.55 r90 bottom
R232_3 "*" R01005 20.125,23.35 r180 bottom
R233 "*" R01005 17.675,29.225 r90 bottom
R233_1 "*" R01005 23.05,29.225 r90 bottom
R233_1_1 "*" R01005 23.05,13.55 r90 bottom
R233_2 "*" R01005 17.675,13.55 r90 bottom
R233_3 "*" R01005 20.125,23.85 r180 bottom
R234 "*" R01005 18.175,29.225 r90 bottom
R234_1 "*" R01005 23.55,29.225 r90 bottom
R234_1_1 "*" R01005 23.55,13.55 r90 bottom
R234_2 "*" R01005 18.175,13.55 r90 bottom
R234_3 "*" R01005 20.125,24.35 r180 bottom
R235 "*" R01005 18.675,29.225 r90 bottom
R235_1 "*" R01005 24.05,29.225 r90 bottom
R235_1_1 "*" R01005 24.05,13.55 r90 bottom
R235_2 "*" R01005 18.675,13.55 r90 bottom
R235_3 "*" R01005 20.125,24.85 r180 bottom
R236 "*" R01005 15.175,33.225 r90 bottom
R236_1 "*" R01005 20.55,33.225 r90 bottom
R236_1_1 "*" R01005 20.55,17.55 r90 bottom
R236_2 "*" R01005 15.175,17.55 r90 bottom
R236_3 "*" R01005 16.125,21.35 r180 bottom
R236_3_1 "*" R01005 16.125,19.35 r180 bottom
R237 "*" R01005 16.675,33.225 r90 bottom
R237_1 "*" R01005 22.05,33.225 r90 bottom
R237_1_1 "*" R01005 22.05,17.55 r90 bottom
R237_2 "*" R01005 16.675,17.55 r90 bottom
R237_3 "*" R01005 16.125,22.85 r180 bottom
R237_3_1 "*" R01005 16.125,20.85 r180 bottom
R238 "*" R01005 15.175,30.825 r90 bottom
R238_1 "*" R01005 20.55,30.825 r90 bottom
R238_1_1 "*" R01005 20.55,15.15 r90 bottom
R238_2 "*" R01005 15.175,15.15 r90 bottom
R238_3 "*" R01005 18.525,21.35 r180 bottom
R238_3_1 "*" R01005 18.525,19.35 r180 bottom
R239 "*" R01005 19.675,31.625 r90 bottom
R239_1 "*" R01005 25.05,31.625 r90 bottom
R239_1_1 "*" R01005 25.05,15.95 r90 bottom
R239_2 "*" R01005 19.675,15.95 r90 bottom
R239_3 "*" R01005 17.725,25.85 r180 bottom
R240 "*" R01005 16.675,30.825 r90 bottom
R240_1 "*" R01005 22.05,30.825 r90 bottom
R240_1_1 "*" R01005 22.05,15.15 r90 bottom
R240_2 "*" R01005 16.675,15.15 r90 bottom
R240_3 "*" R01005 18.525,22.85 r180 bottom
R240_3_1 "*" R01005 18.525,20.85 r180 bottom
R241 "*" R01005 15.175,26.825 r90 bottom
R241_1 "*" R01005 20.55,26.825 r90 bottom
R241_1_1 "*" R01005 20.55,11.15 r90 bottom
R241_2 "*" R01005 15.175,11.15 r90 bottom
R241_3 "*" R01005 22.525,21.35 r180 bottom
R241_3_1 "*" R01005 24.925,21.35 r180 bottom
R241_3_1_1 "*" R01005 24.925,19.35 r180 bottom
R241_3_2 "*" R01005 22.525,19.35 r180 bottom
R242 "*" R01005 16.175,26.825 r90 bottom
R242_1 "*" R01005 21.55,26.825 r90 bottom
R242_1_1 "*" R01005 21.55,11.15 r90 bottom
R242_2 "*" R01005 16.175,11.15 r90 bottom
R242_3 "*" R01005 22.525,22.35 r180 bottom
R242_3_1 "*" R01005 24.925,22.35 r180 bottom
R242_3_1_1 "*" R01005 24.925,20.35 r180 bottom
R242_3_2 "*" R01005 22.525,20.35 r180 bottom
R243 "*" R01005 17.175,26.825 r90 bottom
R243_1 "*" R01005 22.55,26.825 r90 bottom
R243_1_1 "*" R01005 22.55,11.15 r90 bottom
R243_2 "*" R01005 17.175,11.15 r90 bottom
R243_3 "*" R01005 22.525,23.35 r180 bottom
R243_3_1 "*" R01005 24.925,23.35 r180 bottom
R244 "*" R01005 19.175,34.025 r90 bottom
R244_1 "*" R01005 24.55,34.025 r90 bottom
R244_1_1 "*" R01005 24.55,18.35 r90 bottom
R244_2 "*" R01005 19.175,18.35 r90 bottom
R244_3 "*" R01005 15.325,25.35 r180 bottom
R245 "*" R01005 19.675,34.025 r90 bottom
R245_1 "*" R01005 25.05,34.025 r90 bottom
R245_1_1 "*" R01005 25.05,18.35 r90 bottom
R245_2 "*" R01005 19.675,18.35 r90 bottom
R245_3 "*" R01005 15.325,25.85 r180 bottom
R246 "*" R01005 19.675,30.025 r90 bottom
R246_1 "*" R01005 25.05,30.025 r90 bottom
R246_1_1 "*" R01005 25.05,14.35 r90 bottom
R246_2 "*" R01005 19.675,14.35 r90 bottom
R246_3 "*" R01005 19.325,25.85 r180 bottom
R247 "*" R01005 15.675,29.225 r90 bottom
R247_1 "*" R01005 21.05,29.225 r90 bottom
R247_1_1 "*" R01005 21.05,13.55 r90 bottom
R247_2 "*" R01005 15.675,13.55 r90 bottom
R247_3 "*" R01005 20.125,21.85 r180 bottom
R247_3_1 "*" R01005 20.125,19.85 r180 bottom
R248 "*" R01005 16.175,29.225 r90 bottom
R248_1 "*" R01005 21.55,29.225 r90 bottom
R248_1_1 "*" R01005 21.55,13.55 r90 bottom
R248_2 "*" R01005 16.175,13.55 r90 bottom
R248_3 "*" R01005 20.125,22.35 r180 bottom
R248_3_1 "*" R01005 20.125,20.35 r180 bottom
R249 "*" R01005 16.675,29.225 r90 bottom
R249_1 "*" R01005 22.05,29.225 r90 bottom
R249_1_1 "*" R01005 22.05,13.55 r90 bottom
R249_2 "*" R01005 16.675,13.55 r90 bottom
R249_3 "*" R01005 20.125,22.85 r180 bottom
R249_3_1 "*" R01005 20.125,20.85 r180 bottom
R250 "*" R01005 19.675,27.625 r90 bottom
R250_1 "*" R01005 25.05,27.625 r90 bottom
R250_1_1 "*" R01005 25.05,11.95 r90 bottom
R250_2 "*" R01005 19.675,11.95 r90 bottom
R250_3 "*" R01005 21.725,25.85 r180 bottom
R250_3_1 "*" R01005 24.125,25.85 r180 bottom
R251 "*" R01005 18.675,34.025 r90 bottom
R251_1 "*" R01005 24.05,34.025 r90 bottom
R251_1_1 "*" R01005 24.05,18.35 r90 bottom
R251_2 "*" R01005 18.675,18.35 r90 bottom
R251_3 "*" R01005 15.325,24.85 r180 bottom
R252 "*" R01005 16.175,31.625 r90 bottom
R252_1 "*" R01005 21.55,31.625 r90 bottom
R252_1_1 "*" R01005 21.55,15.95 r90 bottom
R252_2 "*" R01005 16.175,15.95 r90 bottom
R252_3 "*" R01005 17.725,22.35 r180 bottom
R252_3_1 "*" R01005 17.725,20.35 r180 bottom
R253 "*" R01005 16.675,31.625 r90 bottom
R253_1 "*" R01005 22.05,31.625 r90 bottom
R253_1_1 "*" R01005 22.05,15.95 r90 bottom
R253_2 "*" R01005 16.675,15.95 r90 bottom
R253_3 "*" R01005 17.725,22.85 r180 bottom
R253_3_1 "*" R01005 17.725,20.85 r180 bottom
R254 "*" R01005 18.175,31.625 r90 bottom
R254_1 "*" R01005 23.55,31.625 r90 bottom
R254_1_1 "*" R01005 23.55,15.95 r90 bottom
R254_2 "*" R01005 18.175,15.95 r90 bottom
R254_3 "*" R01005 17.725,24.35 r180 bottom
R255 "*" R01005 18.675,31.625 r90 bottom
R255_1 "*" R01005 24.05,31.625 r90 bottom
R255_1_1 "*" R01005 24.05,15.95 r90 bottom
R255_2 "*" R01005 18.675,15.95 r90 bottom
R255_3 "*" R01005 17.725,24.85 r180 bottom
R256 "*" R01005 17.175,27.625 r90 bottom
R256_1 "*" R01005 22.55,27.625 r90 bottom
R256_1_1 "*" R01005 22.55,11.95 r90 bottom
R256_2 "*" R01005 17.175,11.95 r90 bottom
R256_3 "*" R01005 21.725,23.35 r180 bottom
R256_3_1 "*" R01005 24.125,23.35 r180 bottom
R257 "*" R01005 18.175,27.625 r90 bottom
R257_1 "*" R01005 23.55,27.625 r90 bottom
R257_1_1 "*" R01005 23.55,11.95 r90 bottom
R257_2 "*" R01005 18.175,11.95 r90 bottom
R257_3 "*" R01005 21.725,24.35 r180 bottom
R257_3_1 "*" R01005 24.125,24.35 r180 bottom
R258 "*" R01005 17.175,34.025 r90 bottom
R258_1 "*" R01005 22.55,34.025 r90 bottom
R258_1_1 "*" R01005 22.55,18.35 r90 bottom
R258_2 "*" R01005 17.175,18.35 r90 bottom
R258_3 "*" R01005 15.325,23.35 r180 bottom
R259 "*" R01005 17.675,34.025 r90 bottom
R259_1 "*" R01005 23.05,34.025 r90 bottom
R259_1_1 "*" R01005 23.05,18.35 r90 bottom
R259_2 "*" R01005 17.675,18.35 r90 bottom
R259_3 "*" R01005 15.325,23.85 r180 bottom
R260 "*" R01005 18.175,34.025 r90 bottom
R260_1 "*" R01005 23.55,34.025 r90 bottom
R260_1_1 "*" R01005 23.55,18.35 r90 bottom
R260_2 "*" R01005 18.175,18.35 r90 bottom
R260_3 "*" R01005 15.325,24.35 r180 bottom
R261 "*" R01005 18.675,30.025 r90 bottom
R261_1 "*" R01005 24.05,30.025 r90 bottom
R261_1_1 "*" R01005 24.05,14.35 r90 bottom
R261_2 "*" R01005 18.675,14.35 r90 bottom
R261_3 "*" R01005 19.325,24.85 r180 bottom
R262 "*" R01005 19.175,30.025 r90 bottom
R262_1 "*" R01005 24.55,30.025 r90 bottom
R262_1_1 "*" R01005 24.55,14.35 r90 bottom
R262_2 "*" R01005 19.175,14.35 r90 bottom
R262_3 "*" R01005 19.325,25.35 r180 bottom
R263 "*" R01005 15.175,29.225 r90 bottom
R263_1 "*" R01005 20.55,29.225 r90 bottom
R263_1_1 "*" R01005 20.55,13.55 r90 bottom
R263_2 "*" R01005 15.175,13.55 r90 bottom
R263_3 "*" R01005 20.125,21.35 r180 bottom
R263_3_1 "*" R01005 20.125,19.35 r180 bottom
R264 "*" R01005 15.675,27.625 r90 bottom
R264_1 "*" R01005 21.05,27.625 r90 bottom
R264_1_1 "*" R01005 21.05,11.95 r90 bottom
R264_2 "*" R01005 15.675,11.95 r90 bottom
R264_3 "*" R01005 21.725,21.85 r180 bottom
R264_3_1 "*" R01005 24.125,21.85 r180 bottom
R264_3_1_1 "*" R01005 24.125,19.85 r180 bottom
R264_3_2 "*" R01005 21.725,19.85 r180 bottom
R265 "*" R01005 16.675,27.625 r90 bottom
R265_1 "*" R01005 22.05,27.625 r90 bottom
R265_1_1 "*" R01005 22.05,11.95 r90 bottom
R265_2 "*" R01005 16.675,11.95 r90 bottom
R265_3 "*" R01005 21.725,22.85 r180 bottom
R265_3_1 "*" R01005 24.125,22.85 r180 bottom
R265_3_1_1 "*" R01005 24.125,20.85 r180 bottom
R265_3_2 "*" R01005 21.725,20.85 r180 bottom
R266 "*" R01005 15.175,31.625 r90 bottom
R266_1 "*" R01005 20.55,31.625 r90 bottom
R266_1_1 "*" R01005 20.55,15.95 r90 bottom
R266_2 "*" R01005 15.175,15.95 r90 bottom
R266_3 "*" R01005 17.725,21.35 r180 bottom
R266_3_1 "*" R01005 17.725,19.35 r180 bottom
R267 "*" R01005 15.675,31.625 r90 bottom
R267_1 "*" R01005 21.05,31.625 r90 bottom
R267_1_1 "*" R01005 21.05,15.95 r90 bottom
R267_2 "*" R01005 15.675,15.95 r90 bottom
R267_3 "*" R01005 17.725,21.85 r180 bottom
R267_3_1 "*" R01005 17.725,19.85 r180 bottom
R268 "*" R01005 17.175,31.625 r90 bottom
R268_1 "*" R01005 22.55,31.625 r90 bottom
R268_1_1 "*" R01005 22.55,15.95 r90 bottom
R268_2 "*" R01005 17.175,15.95 r90 bottom
R268_3 "*" R01005 17.725,23.35 r180 bottom
R269 "*" R01005 17.675,31.625 r90 bottom
R269_1 "*" R01005 23.05,31.625 r90 bottom
R269_1_1 "*" R01005 23.05,15.95 r90 bottom
R269_2 "*" R01005 17.675,15.95 r90 bottom
R269_3 "*" R01005 17.725,23.85 r180 bottom
R270 "*" R01005 18.175,30.025 r90 bottom
R270_1 "*" R01005 23.55,30.025 r90 bottom
R270_1_1 "*" R01005 23.55,14.35 r90 bottom
R270_2 "*" R01005 18.175,14.35 r90 bottom
R270_3 "*" R01005 19.325,24.35 r180 bottom
R271 "*" R01005 16.675,26.825 r90 bottom
R271_1 "*" R01005 22.05,26.825 r90 bottom
R271_1_1 "*" R01005 22.05,11.15 r90 bottom
R271_2 "*" R01005 16.675,11.15 r90 bottom
R271_3 "*" R01005 22.525,22.85 r180 bottom
R271_3_1 "*" R01005 24.925,22.85 r180 bottom
R271_3_1_1 "*" R01005 24.925,20.85 r180 bottom
R271_3_2 "*" R01005 22.525,20.85 r180 bottom
R272 "*" R01005 15.175,34.025 r90 bottom
R272_1 "*" R01005 20.55,34.025 r90 bottom
R272_1_1 "*" R01005 20.55,18.35 r90 bottom
R272_2 "*" R01005 15.175,18.35 r90 bottom
R272_3 "*" R01005 15.325,21.35 r180 bottom
R272_3_1 "*" R01005 15.325,19.35 r180 bottom
R273 "*" R01005 15.675,34.025 r90 bottom
R273_1 "*" R01005 21.05,34.025 r90 bottom
R273_1_1 "*" R01005 21.05,18.35 r90 bottom
R273_2 "*" R01005 15.675,18.35 r90 bottom
R273_3 "*" R01005 15.325,21.85 r180 bottom
R273_3_1 "*" R01005 15.325,19.85 r180 bottom
R274 "*" R01005 16.175,34.025 r90 bottom
R274_1 "*" R01005 21.55,34.025 r90 bottom
R274_1_1 "*" R01005 21.55,18.35 r90 bottom
R274_2 "*" R01005 16.175,18.35 r90 bottom
R274_3 "*" R01005 15.325,22.35 r180 bottom
R274_3_1 "*" R01005 15.325,20.35 r180 bottom
R275 "*" R01005 16.675,34.025 r90 bottom
R275_1 "*" R01005 22.05,34.025 r90 bottom
R275_1_1 "*" R01005 22.05,18.35 r90 bottom
R275_2 "*" R01005 16.675,18.35 r90 bottom
R275_3 "*" R01005 15.325,22.85 r180 bottom
R275_3_1 "*" R01005 15.325,20.85 r180 bottom
R276 "*" R01005 16.675,28.425 r90 bottom
R276_1 "*" R01005 22.05,28.425 r90 bottom
R276_1_1 "*" R01005 22.05,12.75 r90 bottom
R276_2 "*" R01005 16.675,12.75 r90 bottom
R276_3 "*" R01005 20.925,22.85 r180 bottom
R276_3_1 "*" R01005 23.325,22.85 r180 bottom
R276_3_1_1 "*" R01005 23.325,20.85 r180 bottom
R276_3_2 "*" R01005 20.925,20.85 r180 bottom
R277 "*" R01005 17.175,28.425 r90 bottom
R277_1 "*" R01005 22.55,28.425 r90 bottom
R277_1_1 "*" R01005 22.55,12.75 r90 bottom
R277_2 "*" R01005 17.175,12.75 r90 bottom
R277_3 "*" R01005 20.925,23.35 r180 bottom
R277_3_1 "*" R01005 23.325,23.35 r180 bottom
R278 "*" R01005 17.675,28.425 r90 bottom
R278_1 "*" R01005 23.05,28.425 r90 bottom
R278_1_1 "*" R01005 23.05,12.75 r90 bottom
R278_2 "*" R01005 17.675,12.75 r90 bottom
R278_3 "*" R01005 20.925,23.85 r180 bottom
R278_3_1 "*" R01005 23.325,23.85 r180 bottom
R279 "*" R01005 19.175,27.625 r90 bottom
R279_1 "*" R01005 24.55,27.625 r90 bottom
R279_1_1 "*" R01005 24.55,11.95 r90 bottom
R279_2 "*" R01005 19.175,11.95 r90 bottom
R279_3 "*" R01005 21.725,25.35 r180 bottom
R279_3_1 "*" R01005 24.125,25.35 r180 bottom
R280 "*" R01005 15.675,26.825 r90 bottom
R280_1 "*" R01005 21.05,26.825 r90 bottom
R280_1_1 "*" R01005 21.05,11.15 r90 bottom
R280_2 "*" R01005 15.675,11.15 r90 bottom
R280_3 "*" R01005 22.525,21.85 r180 bottom
R280_3_1 "*" R01005 24.925,21.85 r180 bottom
R280_3_1_1 "*" R01005 24.925,19.85 r180 bottom
R280_3_2 "*" R01005 22.525,19.85 r180 bottom
R281 "*" R01005 18.675,30.825 r90 bottom
R281_1 "*" R01005 24.05,30.825 r90 bottom
R281_1_1 "*" R01005 24.05,15.15 r90 bottom
R281_2 "*" R01005 18.675,15.15 r90 bottom
R281_3 "*" R01005 18.525,24.85 r180 bottom
R282 "*" R01005 19.175,30.825 r90 bottom
R282_1 "*" R01005 24.55,30.825 r90 bottom
R282_1_1 "*" R01005 24.55,15.15 r90 bottom
R282_2 "*" R01005 19.175,15.15 r90 bottom
R282_3 "*" R01005 18.525,25.35 r180 bottom
R283 "*" R01005 19.675,30.825 r90 bottom
R283_1 "*" R01005 25.05,30.825 r90 bottom
R283_1_1 "*" R01005 25.05,15.15 r90 bottom
R283_2 "*" R01005 19.675,15.15 r90 bottom
R283_3 "*" R01005 18.525,25.85 r180 bottom
R284 "*" R01005 17.175,30.025 r90 bottom
R284_1 "*" R01005 22.55,30.025 r90 bottom
R284_1_1 "*" R01005 22.55,14.35 r90 bottom
R284_2 "*" R01005 17.175,14.35 r90 bottom
R284_3 "*" R01005 19.325,23.35 r180 bottom
R285 "*" R01005 16.175,28.425 r90 bottom
R285_1 "*" R01005 21.55,28.425 r90 bottom
R285_1_1 "*" R01005 21.55,12.75 r90 bottom
R285_2 "*" R01005 16.175,12.75 r90 bottom
R285_3 "*" R01005 20.925,22.35 r180 bottom
R285_3_1 "*" R01005 23.325,22.35 r180 bottom
R285_3_1_1 "*" R01005 23.325,20.35 r180 bottom
R285_3_2 "*" R01005 20.925,20.35 r180 bottom
R286 "*" R01005 18.175,33.225 r90 bottom
R286_1 "*" R01005 23.55,33.225 r90 bottom
R286_1_1 "*" R01005 23.55,17.55 r90 bottom
R286_2 "*" R01005 18.175,17.55 r90 bottom
R286_3 "*" R01005 16.125,24.35 r180 bottom
R287 "*" R01005 18.675,33.225 r90 bottom
R287_1 "*" R01005 24.05,33.225 r90 bottom
R287_1_1 "*" R01005 24.05,17.55 r90 bottom
R287_2 "*" R01005 18.675,17.55 r90 bottom
R287_3 "*" R01005 16.125,24.85 r180 bottom
R288 "*" R01005 19.175,33.225 r90 bottom
R288_1 "*" R01005 24.55,33.225 r90 bottom
R288_1_1 "*" R01005 24.55,17.55 r90 bottom
R288_2 "*" R01005 19.175,17.55 r90 bottom
R288_3 "*" R01005 16.125,25.35 r180 bottom
R289 "*" R01005 15.175,32.425 r90 bottom
R289_1 "*" R01005 20.55,32.425 r90 bottom
R289_1_1 "*" R01005 20.55,16.75 r90 bottom
R289_2 "*" R01005 15.175,16.75 r90 bottom
R289_3 "*" R01005 16.925,21.35 r180 bottom
R289_3_1 "*" R01005 16.925,19.35 r180 bottom
R290 "*" R01005 18.175,30.825 r90 bottom
R290_1 "*" R01005 23.55,30.825 r90 bottom
R290_1_1 "*" R01005 23.55,15.15 r90 bottom
R290_2 "*" R01005 18.175,15.15 r90 bottom
R290_3 "*" R01005 18.525,24.35 r180 bottom
R291 "*" R01005 18.175,28.425 r90 bottom
R291_1 "*" R01005 23.55,28.425 r90 bottom
R291_1_1 "*" R01005 23.55,12.75 r90 bottom
R291_2 "*" R01005 18.175,12.75 r90 bottom
R291_3 "*" R01005 20.925,24.35 r180 bottom
R291_3_1 "*" R01005 23.325,24.35 r180 bottom
R292 "*" R01005 18.675,28.425 r90 bottom
R292_1 "*" R01005 24.05,28.425 r90 bottom
R292_1_1 "*" R01005 24.05,12.75 r90 bottom
R292_2 "*" R01005 18.675,12.75 r90 bottom
R292_3 "*" R01005 20.925,24.85 r180 bottom
R292_3_1 "*" R01005 23.325,24.85 r180 bottom
R293 "*" R01005 19.175,28.425 r90 bottom
R293_1 "*" R01005 24.55,28.425 r90 bottom
R293_1_1 "*" R01005 24.55,12.75 r90 bottom
R293_2 "*" R01005 19.175,12.75 r90 bottom
R293_3 "*" R01005 20.925,25.35 r180 bottom
R293_3_1 "*" R01005 23.325,25.35 r180 bottom
R294 "*" R01005 19.675,28.425 r90 bottom
R294_1 "*" R01005 25.05,28.425 r90 bottom
R294_1_1 "*" R01005 25.05,12.75 r90 bottom
R294_2 "*" R01005 19.675,12.75 r90 bottom
R294_3 "*" R01005 20.925,25.85 r180 bottom
R294_3_1 "*" R01005 23.325,25.85 r180 bottom
R295 "*" R01005 19.175,26.825 r90 bottom
R295_1 "*" R01005 24.55,26.825 r90 bottom
R295_1_1 "*" R01005 24.55,11.15 r90 bottom
R295_2 "*" R01005 19.175,11.15 r90 bottom
R295_3 "*" R01005 22.525,25.35 r180 bottom
R295_3_1 "*" R01005 24.925,25.35 r180 bottom
R296 "*" R01005 15.175,30.025 r90 bottom
R296_1 "*" R01005 20.55,30.025 r90 bottom
R296_1_1 "*" R01005 20.55,14.35 r90 bottom
R296_2 "*" R01005 15.175,14.35 r90 bottom
R296_3 "*" R01005 19.325,21.35 r180 bottom
R296_3_1 "*" R01005 19.325,19.35 r180 bottom
R297 "*" R01005 15.675,30.025 r90 bottom
R297_1 "*" R01005 21.05,30.025 r90 bottom
R297_1_1 "*" R01005 21.05,14.35 r90 bottom
R297_2 "*" R01005 15.675,14.35 r90 bottom
R297_3 "*" R01005 19.325,21.85 r180 bottom
R297_3_1 "*" R01005 19.325,19.85 r180 bottom
R298 "*" R01005 16.175,30.025 r90 bottom
R298_1 "*" R01005 21.55,30.025 r90 bottom
R298_1_1 "*" R01005 21.55,14.35 r90 bottom
R298_2 "*" R01005 16.175,14.35 r90 bottom
R298_3 "*" R01005 19.325,22.35 r180 bottom
R298_3_1 "*" R01005 19.325,20.35 r180 bottom
R299 "*" R01005 16.675,30.025 r90 bottom
R299_1 "*" R01005 22.05,30.025 r90 bottom
R299_1_1 "*" R01005 22.05,14.35 r90 bottom
R299_2 "*" R01005 16.675,14.35 r90 bottom
R299_3 "*" R01005 19.325,22.85 r180 bottom
R299_3_1 "*" R01005 19.325,20.85 r180 bottom
R300 "*" R01005 17.675,30.025 r90 bottom
R300_1 "*" R01005 23.05,30.025 r90 bottom
R300_1_1 "*" R01005 23.05,14.35 r90 bottom
R300_2 "*" R01005 17.675,14.35 r90 bottom
R300_3 "*" R01005 19.325,23.85 r180 bottom
R301 "*" R01005 15.675,32.425 r90 bottom
R301_1 "*" R01005 21.05,32.425 r90 bottom
R301_1_1 "*" R01005 21.05,16.75 r90 bottom
R301_2 "*" R01005 15.675,16.75 r90 bottom
R301_3 "*" R01005 16.925,21.85 r180 bottom
R301_3_1 "*" R01005 16.925,19.85 r180 bottom
R302 "*" R01005 19.675,33.225 r90 bottom
R302_1 "*" R01005 25.05,33.225 r90 bottom
R302_1_1 "*" R01005 25.05,17.55 r90 bottom
R302_2 "*" R01005 19.675,17.55 r90 bottom
R302_3 "*" R01005 16.125,25.85 r180 bottom
R303 "*" R01005 17.175,32.425 r90 bottom
R303_1 "*" R01005 22.55,32.425 r90 bottom
R303_1_1 "*" R01005 22.55,16.75 r90 bottom
R303_2 "*" R01005 17.175,16.75 r90 bottom
R303_3 "*" R01005 16.925,23.35 r180 bottom
R304 "*" R01005 16.175,32.425 r90 bottom
R304_1 "*" R01005 21.55,32.425 r90 bottom
R304_1_1 "*" R01005 21.55,16.75 r90 bottom
R304_2 "*" R01005 16.175,16.75 r90 bottom
R304_3 "*" R01005 16.925,22.35 r180 bottom
R304_3_1 "*" R01005 16.925,20.35 r180 bottom
R305 "*" R01005 16.675,32.425 r90 bottom
R305_1 "*" R01005 22.05,32.425 r90 bottom
R305_1_1 "*" R01005 22.05,16.75 r90 bottom
R305_2 "*" R01005 16.675,16.75 r90 bottom
R305_3 "*" R01005 16.925,22.85 r180 bottom
R305_3_1 "*" R01005 16.925,20.85 r180 bottom
R306 "*" R01005 17.675,32.425 r90 bottom
R306_1 "*" R01005 23.05,32.425 r90 bottom
R306_1_1 "*" R01005 23.05,16.75 r90 bottom
R306_2 "*" R01005 17.675,16.75 r90 bottom
R306_3 "*" R01005 16.925,23.85 r180 bottom
R307 "*" R01005 18.675,32.425 r90 bottom
R307_1 "*" R01005 24.05,32.425 r90 bottom
R307_1_1 "*" R01005 24.05,16.75 r90 bottom
R307_2 "*" R01005 18.675,16.75 r90 bottom
R307_3 "*" R01005 16.925,24.85 r180 bottom
R308 "*" R01005 19.675,32.425 r90 bottom
R308_1 "*" R01005 25.05,32.425 r90 bottom
R308_1_1 "*" R01005 25.05,16.75 r90 bottom
R308_2 "*" R01005 19.675,16.75 r90 bottom
R308_3 "*" R01005 16.925,25.85 r180 bottom
R309 "*" R01005 18.175,32.425 r90 bottom
R309_1 "*" R01005 23.55,32.425 r90 bottom
R309_1_1 "*" R01005 23.55,16.75 r90 bottom
R309_2 "*" R01005 18.175,16.75 r90 bottom
R309_3 "*" R01005 16.925,24.35 r180 bottom
R310 "*" R01005 19.175,32.425 r90 bottom
R310_1 "*" R01005 24.55,32.425 r90 bottom
R310_1_1 "*" R01005 24.55,16.75 r90 bottom
R310_2 "*" R01005 19.175,16.75 r90 bottom
R310_3 "*" R01005 16.925,25.35 r180 bottom
R311 "*" R0201_nosilk 34.425,27.25 r90 bottom
R311_1 "*" R0201_nosilk 41.325,27.25 r90 bottom
R311_2 "*" R0201_nosilk 34.425,14.6 r90 bottom
R311_2_1 "*" R0201_nosilk 41.325,14.6 r90 bottom
R312 "*" R0201_nosilk 32.025,25.05 r90 bottom
R312_1 "*" R0201_nosilk 38.925,25.05 r90 bottom
R312_2 "*" R0201_nosilk 32.025,12.4 r90 bottom
R312_2_1 "*" R0201_nosilk 38.925,12.4 r90 bottom
R313 "*" R0201_nosilk 33.225,26.15 r90 bottom
R313_1 "*" R0201_nosilk 40.125,26.15 r90 bottom
R313_2 "*" R0201_nosilk 33.225,13.5 r90 bottom
R313_2_1 "*" R0201_nosilk 40.125,13.5 r90 bottom
R314 "*" R0201_nosilk 30.225,25.05 r90 bottom
R314_1 "*" R0201_nosilk 37.125,25.05 r90 bottom
R314_2 "*" R0201_nosilk 30.225,12.4 r90 bottom
R314_2_1 "*" R0201_nosilk 37.125,12.4 r90 bottom
R315 "*" R0201_nosilk 33.225,25.05 r90 bottom
R315_1 "*" R0201_nosilk 40.125,25.05 r90 bottom
R315_2 "*" R0201_nosilk 33.225,12.4 r90 bottom
R315_2_1 "*" R0201_nosilk 40.125,12.4 r90 bottom
R316 "*" R0201_nosilk 29.625,31.65 r90 bottom
R316_1 "*" R0201_nosilk 36.525,31.65 r90 bottom
R316_2 "*" R0201_nosilk 29.625,19 r90 bottom
R316_2_1 "*" R0201_nosilk 36.525,19 r90 bottom
R317 "*" R0201_nosilk 30.825,31.65 r90 bottom
R317_1 "*" R0201_nosilk 37.725,31.65 r90 bottom
R317_2 "*" R0201_nosilk 30.825,19 r90 bottom
R317_2_1 "*" R0201_nosilk 37.725,19 r90 bottom
R318 "*" R0201_nosilk 33.225,31.65 r90 bottom
R318_1 "*" R0201_nosilk 40.125,31.65 r90 bottom
R318_2 "*" R0201_nosilk 33.225,19 r90 bottom
R318_2_1 "*" R0201_nosilk 40.125,19 r90 bottom
R319 "*" R0201_nosilk 33.825,27.25 r90 bottom
R319_1 "*" R0201_nosilk 40.725,27.25 r90 bottom
R319_2 "*" R0201_nosilk 33.825,14.6 r90 bottom
R319_2_1 "*" R0201_nosilk 40.725,14.6 r90 bottom
R320 "*" R0201_nosilk 30.225,26.15 r90 bottom
R320_1 "*" R0201_nosilk 37.125,26.15 r90 bottom
R320_2 "*" R0201_nosilk 30.225,13.5 r90 bottom
R320_2_1 "*" R0201_nosilk 37.125,13.5 r90 bottom
R321 "*" R0201_nosilk 31.425,27.25 r90 bottom
R321_1 "*" R0201_nosilk 38.325,27.25 r90 bottom
R321_2 "*" R0201_nosilk 31.425,14.6 r90 bottom
R321_2_1 "*" R0201_nosilk 38.325,14.6 r90 bottom
R322 "*" R0201_nosilk 31.425,25.05 r90 bottom
R322_1 "*" R0201_nosilk 38.325,25.05 r90 bottom
R322_2 "*" R0201_nosilk 31.425,12.4 r90 bottom
R322_2_1 "*" R0201_nosilk 38.325,12.4 r90 bottom
R323 "*" R0201_nosilk 34.425,26.15 r90 bottom
R323_1 "*" R0201_nosilk 41.325,26.15 r90 bottom
R323_2 "*" R0201_nosilk 34.425,13.5 r90 bottom
R323_2_1 "*" R0201_nosilk 41.325,13.5 r90 bottom
R324 "*" R0201_nosilk 29.625,25.05 r90 bottom
R324_1 "*" R0201_nosilk 36.525,25.05 r90 bottom
R324_2 "*" R0201_nosilk 29.625,12.4 r90 bottom
R324_2_1 "*" R0201_nosilk 36.525,12.4 r90 bottom
R325 "*" R0201_nosilk 33.825,25.05 r90 bottom
R325_1 "*" R0201_nosilk 40.725,25.05 r90 bottom
R325_2 "*" R0201_nosilk 33.825,12.4 r90 bottom
R325_2_1 "*" R0201_nosilk 40.725,12.4 r90 bottom
R326 "*" R0201_nosilk 30.825,32.75 r90 bottom
R326_1 "*" R0201_nosilk 37.725,32.75 r90 bottom
R326_2 "*" R0201_nosilk 30.825,20.1 r90 bottom
R326_2_1 "*" R0201_nosilk 37.725,20.1 r90 bottom
R327 "*" R0201_nosilk 31.425,32.75 r90 bottom
R327_1 "*" R0201_nosilk 38.325,32.75 r90 bottom
R327_2 "*" R0201_nosilk 31.425,20.1 r90 bottom
R327_2_1 "*" R0201_nosilk 38.325,20.1 r90 bottom
R328 "*" R0201_nosilk 32.025,32.75 r90 bottom
R328_1 "*" R0201_nosilk 38.925,32.75 r90 bottom
R328_2 "*" R0201_nosilk 32.025,20.1 r90 bottom
R328_2_1 "*" R0201_nosilk 38.925,20.1 r90 bottom
R329 "*" R0201_nosilk 31.425,28.35 r90 bottom
R329_1 "*" R0201_nosilk 38.325,28.35 r90 bottom
R329_2 "*" R0201_nosilk 31.425,15.7 r90 bottom
R329_2_1 "*" R0201_nosilk 38.325,15.7 r90 bottom
R330 "*" R0201_nosilk 35.025,28.35 r90 bottom
R330_1 "*" R0201_nosilk 41.925,28.35 r90 bottom
R330_2 "*" R0201_nosilk 35.025,15.7 r90 bottom
R330_2_1 "*" R0201_nosilk 41.925,15.7 r90 bottom
R331 "*" R0201_nosilk 34.425,28.35 r90 bottom
R331_1 "*" R0201_nosilk 41.325,28.35 r90 bottom
R331_2 "*" R0201_nosilk 34.425,15.7 r90 bottom
R331_2_1 "*" R0201_nosilk 41.325,15.7 r90 bottom
R332 "*" R0201_nosilk 30.825,25.05 r90 bottom
R332_1 "*" R0201_nosilk 37.725,25.05 r90 bottom
R332_2 "*" R0201_nosilk 30.825,12.4 r90 bottom
R332_2_1 "*" R0201_nosilk 37.725,12.4 r90 bottom
R333 "*" R0201_nosilk 33.825,26.15 r90 bottom
R333_1 "*" R0201_nosilk 40.725,26.15 r90 bottom
R333_2 "*" R0201_nosilk 33.825,13.5 r90 bottom
R333_2_1 "*" R0201_nosilk 40.725,13.5 r90 bottom
R334 "*" R0201_nosilk 35.025,26.15 r90 bottom
R334_1 "*" R0201_nosilk 41.925,26.15 r90 bottom
R334_2 "*" R0201_nosilk 35.025,13.5 r90 bottom
R334_2_1 "*" R0201_nosilk 41.925,13.5 r90 bottom
R335 "*" R0201_nosilk 32.625,25.05 r90 bottom
R335_1 "*" R0201_nosilk 39.525,25.05 r90 bottom
R335_2 "*" R0201_nosilk 32.625,12.4 r90 bottom
R335_2_1 "*" R0201_nosilk 39.525,12.4 r90 bottom
R336 "*" R0201_nosilk 35.025,33.85 r90 bottom
R336_1 "*" R0201_nosilk 41.925,33.85 r90 bottom
R336_2 "*" R0201_nosilk 35.025,21.2 r90 bottom
R336_2_1 "*" R0201_nosilk 41.925,21.2 r90 bottom
R337 "*" R0201_nosilk 30.225,32.75 r90 bottom
R337_1 "*" R0201_nosilk 37.125,32.75 r90 bottom
R337_2 "*" R0201_nosilk 30.225,20.1 r90 bottom
R337_2_1 "*" R0201_nosilk 37.125,20.1 r90 bottom
R338 "*" R0201_nosilk 29.625,32.75 r90 bottom
R338_1 "*" R0201_nosilk 36.525,32.75 r90 bottom
R338_2 "*" R0201_nosilk 29.625,20.1 r90 bottom
R338_2_1 "*" R0201_nosilk 36.525,20.1 r90 bottom
R339 "*" R0201_nosilk 30.225,28.35 r90 bottom
R339_1 "*" R0201_nosilk 37.125,28.35 r90 bottom
R339_2 "*" R0201_nosilk 30.225,15.7 r90 bottom
R339_2_1 "*" R0201_nosilk 37.125,15.7 r90 bottom
R340 "*" R0201_nosilk 32.025,28.35 r90 bottom
R340_1 "*" R0201_nosilk 38.925,28.35 r90 bottom
R340_2 "*" R0201_nosilk 32.025,15.7 r90 bottom
R340_2_1 "*" R0201_nosilk 38.925,15.7 r90 bottom
R341 "*" R0201_nosilk 33.825,28.35 r90 bottom
R341_1 "*" R0201_nosilk 40.725,28.35 r90 bottom
R341_2 "*" R0201_nosilk 33.825,15.7 r90 bottom
R341_2_1 "*" R0201_nosilk 40.725,15.7 r90 bottom
R342 "*" R0201_nosilk 29.625,26.15 r90 bottom
R342_1 "*" R0201_nosilk 36.525,26.15 r90 bottom
R342_2 "*" R0201_nosilk 29.625,13.5 r90 bottom
R342_2_1 "*" R0201_nosilk 36.525,13.5 r90 bottom
R343 "*" R0201_nosilk 32.025,26.15 r90 bottom
R343_1 "*" R0201_nosilk 38.925,26.15 r90 bottom
R343_2 "*" R0201_nosilk 32.025,13.5 r90 bottom
R343_2_1 "*" R0201_nosilk 38.925,13.5 r90 bottom
R344 "*" R0201_nosilk 31.425,26.15 r90 bottom
R344_1 "*" R0201_nosilk 38.325,26.15 r90 bottom
R344_2 "*" R0201_nosilk 31.425,13.5 r90 bottom
R344_2_1 "*" R0201_nosilk 38.325,13.5 r90 bottom
R345 "*" R0201_nosilk 32.625,26.15 r90 bottom
R345_1 "*" R0201_nosilk 39.525,26.15 r90 bottom
R345_2 "*" R0201_nosilk 32.625,13.5 r90 bottom
R345_2_1 "*" R0201_nosilk 39.525,13.5 r90 bottom
R346 "*" R0201_nosilk 32.625,33.85 r90 bottom
R346_1 "*" R0201_nosilk 39.525,33.85 r90 bottom
R346_2 "*" R0201_nosilk 32.625,21.2 r90 bottom
R346_2_1 "*" R0201_nosilk 39.525,21.2 r90 bottom
R347 "*" R0201_nosilk 33.225,33.85 r90 bottom
R347_1 "*" R0201_nosilk 40.125,33.85 r90 bottom
R347_2 "*" R0201_nosilk 33.225,21.2 r90 bottom
R347_2_1 "*" R0201_nosilk 40.125,21.2 r90 bottom
R348 "*" R0201_nosilk 34.425,33.85 r90 bottom
R348_1 "*" R0201_nosilk 41.325,33.85 r90 bottom
R348_2 "*" R0201_nosilk 34.425,21.2 r90 bottom
R348_2_1 "*" R0201_nosilk 41.325,21.2 r90 bottom
R349 "*" R0201_nosilk 34.425,29.45 r90 bottom
R349_1 "*" R0201_nosilk 41.325,29.45 r90 bottom
R349_2 "*" R0201_nosilk 34.425,16.8 r90 bottom
R349_2_1 "*" R0201_nosilk 41.325,16.8 r90 bottom
R350 "*" R0201_nosilk 30.825,28.35 r90 bottom
R350_1 "*" R0201_nosilk 37.725,28.35 r90 bottom
R350_2 "*" R0201_nosilk 30.825,15.7 r90 bottom
R350_2_1 "*" R0201_nosilk 37.725,15.7 r90 bottom
R351 "*" R0201_nosilk 33.225,28.35 r90 bottom
R351_1 "*" R0201_nosilk 40.125,28.35 r90 bottom
R351_2 "*" R0201_nosilk 33.225,15.7 r90 bottom
R351_2_1 "*" R0201_nosilk 40.125,15.7 r90 bottom
R352 "*" R0201_nosilk 30.825,27.25 r90 bottom
R352_1 "*" R0201_nosilk 37.725,27.25 r90 bottom
R352_2 "*" R0201_nosilk 30.825,14.6 r90 bottom
R352_2_1 "*" R0201_nosilk 37.725,14.6 r90 bottom
R353 "*" R0201_nosilk 32.025,27.25 r90 bottom
R353_1 "*" R0201_nosilk 38.925,27.25 r90 bottom
R353_2 "*" R0201_nosilk 32.025,14.6 r90 bottom
R353_2_1 "*" R0201_nosilk 38.925,14.6 r90 bottom
R354 "*" R0201_nosilk 35.025,27.25 r90 bottom
R354_1 "*" R0201_nosilk 41.925,27.25 r90 bottom
R354_2 "*" R0201_nosilk 35.025,14.6 r90 bottom
R354_2_1 "*" R0201_nosilk 41.925,14.6 r90 bottom
R355 "*" R0201_nosilk 33.225,27.25 r90 bottom
R355_1 "*" R0201_nosilk 40.125,27.25 r90 bottom
R355_2 "*" R0201_nosilk 33.225,14.6 r90 bottom
R355_2_1 "*" R0201_nosilk 40.125,14.6 r90 bottom
R356 "*" R0201_nosilk 32.025,33.85 r90 bottom
R356_1 "*" R0201_nosilk 38.925,33.85 r90 bottom
R356_2 "*" R0201_nosilk 32.025,21.2 r90 bottom
R356_2_1 "*" R0201_nosilk 38.925,21.2 r90 bottom
R357 "*" R0201_nosilk 31.425,33.85 r90 bottom
R357_1 "*" R0201_nosilk 38.325,33.85 r90 bottom
R357_2 "*" R0201_nosilk 31.425,21.2 r90 bottom
R357_2_1 "*" R0201_nosilk 38.325,21.2 r90 bottom
R358 "*" R0201_nosilk 33.825,33.85 r90 bottom
R358_1 "*" R0201_nosilk 40.725,33.85 r90 bottom
R358_2 "*" R0201_nosilk 33.825,21.2 r90 bottom
R358_2_1 "*" R0201_nosilk 40.725,21.2 r90 bottom
R359 "*" R0201_nosilk 33.825,29.45 r90 bottom
R359_1 "*" R0201_nosilk 40.725,29.45 r90 bottom
R359_2 "*" R0201_nosilk 33.825,16.8 r90 bottom
R359_2_1 "*" R0201_nosilk 40.725,16.8 r90 bottom
R360 "*" R0201_nosilk 29.625,28.35 r90 bottom
R360_1 "*" R0201_nosilk 36.525,28.35 r90 bottom
R360_2 "*" R0201_nosilk 29.625,15.7 r90 bottom
R360_2_1 "*" R0201_nosilk 36.525,15.7 r90 bottom
R361 "*" R0201_nosilk 32.625,28.35 r90 bottom
R361_1 "*" R0201_nosilk 39.525,28.35 r90 bottom
R361_2 "*" R0201_nosilk 32.625,15.7 r90 bottom
R361_2_1 "*" R0201_nosilk 39.525,15.7 r90 bottom
R362 "*" R0201_nosilk 30.225,27.25 r90 bottom
R362_1 "*" R0201_nosilk 37.125,27.25 r90 bottom
R362_2 "*" R0201_nosilk 30.225,14.6 r90 bottom
R362_2_1 "*" R0201_nosilk 37.125,14.6 r90 bottom
R363 "*" R0201_nosilk 29.625,27.25 r90 bottom
R363_1 "*" R0201_nosilk 36.525,27.25 r90 bottom
R363_2 "*" R0201_nosilk 29.625,14.6 r90 bottom
R363_2_1 "*" R0201_nosilk 36.525,14.6 r90 bottom
R364 "*" R0201_nosilk 32.625,27.25 r90 bottom
R364_1 "*" R0201_nosilk 39.525,27.25 r90 bottom
R364_2 "*" R0201_nosilk 32.625,14.6 r90 bottom
R364_2_1 "*" R0201_nosilk 39.525,14.6 r90 bottom
R365 "*" R0201_nosilk 30.825,26.15 r90 bottom
R365_1 "*" R0201_nosilk 37.725,26.15 r90 bottom
R365_2 "*" R0201_nosilk 30.825,13.5 r90 bottom
R365_2_1 "*" R0201_nosilk 37.725,13.5 r90 bottom
R366 "*" R0201_nosilk 29.625,33.85 r90 bottom
R366_1 "*" R0201_nosilk 36.525,33.85 r90 bottom
R366_2 "*" R0201_nosilk 29.625,21.2 r90 bottom
R366_2_1 "*" R0201_nosilk 36.525,21.2 r90 bottom
R367 "*" R0201_nosilk 30.225,33.85 r90 bottom
R367_1 "*" R0201_nosilk 37.125,33.85 r90 bottom
R367_2 "*" R0201_nosilk 30.225,21.2 r90 bottom
R367_2_1 "*" R0201_nosilk 37.125,21.2 r90 bottom
R368 "*" R0201_nosilk 30.825,33.85 r90 bottom
R368_1 "*" R0201_nosilk 37.725,33.85 r90 bottom
R368_2 "*" R0201_nosilk 30.825,21.2 r90 bottom
R368_2_1 "*" R0201_nosilk 37.725,21.2 r90 bottom
R369 "*" R0201_nosilk 33.225,29.45 r90 bottom
R369_1 "*" R0201_nosilk 40.125,29.45 r90 bottom
R369_2 "*" R0201_nosilk 33.225,16.8 r90 bottom
R369_2_1 "*" R0201_nosilk 40.125,16.8 r90 bottom
R370 "*" R0201_nosilk 35.025,29.45 r90 bottom
R370_1 "*" R0201_nosilk 41.925,29.45 r90 bottom
R370_2 "*" R0201_nosilk 35.025,16.8 r90 bottom
R370_2_1 "*" R0201_nosilk 41.925,16.8 r90 bottom
R371 "*" R0201_nosilk 31.425,30.55 r90 bottom
R371_1 "*" R0201_nosilk 38.325,30.55 r90 bottom
R371_2 "*" R0201_nosilk 31.425,17.9 r90 bottom
R371_2_1 "*" R0201_nosilk 38.325,17.9 r90 bottom
R372 "*" R0201_nosilk 32.025,30.55 r90 bottom
R372_1 "*" R0201_nosilk 38.925,30.55 r90 bottom
R372_2 "*" R0201_nosilk 32.025,17.9 r90 bottom
R372_2_1 "*" R0201_nosilk 38.925,17.9 r90 bottom
R373 "*" R0201_nosilk 30.225,23.95 r90 bottom
R373_1 "*" R0201_nosilk 37.125,23.95 r90 bottom
R373_2 "*" R0201_nosilk 30.225,11.3 r90 bottom
R373_2_1 "*" R0201_nosilk 37.125,11.3 r90 bottom
R374 "*" R0201_nosilk 34.425,25.05 r90 bottom
R374_1 "*" R0201_nosilk 41.325,25.05 r90 bottom
R374_2 "*" R0201_nosilk 34.425,12.4 r90 bottom
R374_2_1 "*" R0201_nosilk 41.325,12.4 r90 bottom
R375 "*" R0201_nosilk 35.025,25.05 r90 bottom
R375_1 "*" R0201_nosilk 41.925,25.05 r90 bottom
